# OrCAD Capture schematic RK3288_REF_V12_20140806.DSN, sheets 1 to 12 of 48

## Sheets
1 01.Index: title: Index; note: Index
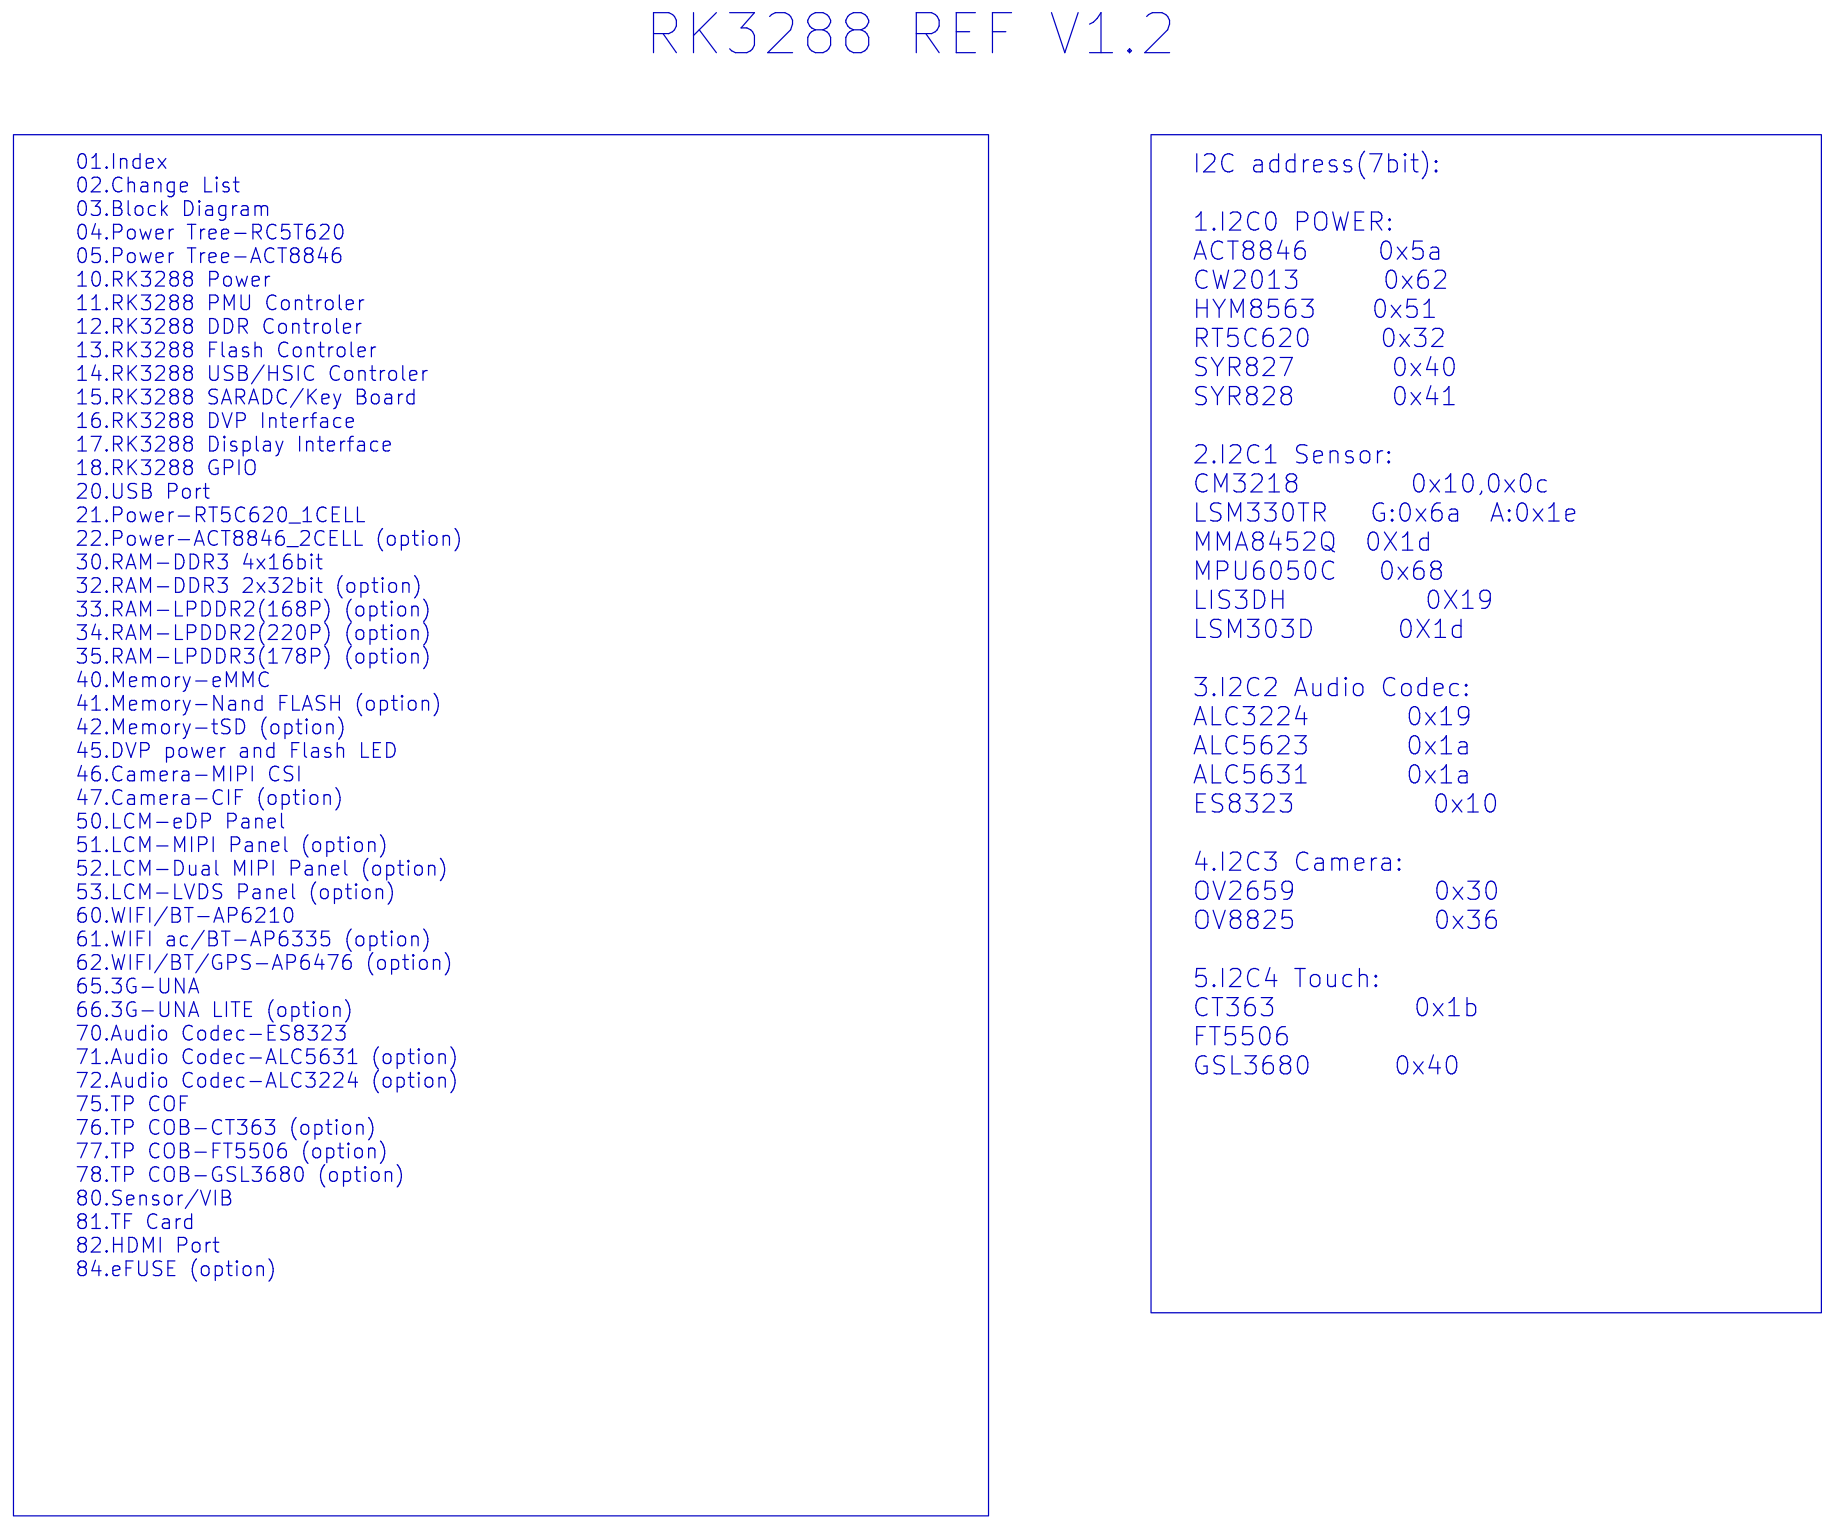
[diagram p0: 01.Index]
2 02.Change List: title: Change List; note: Change List
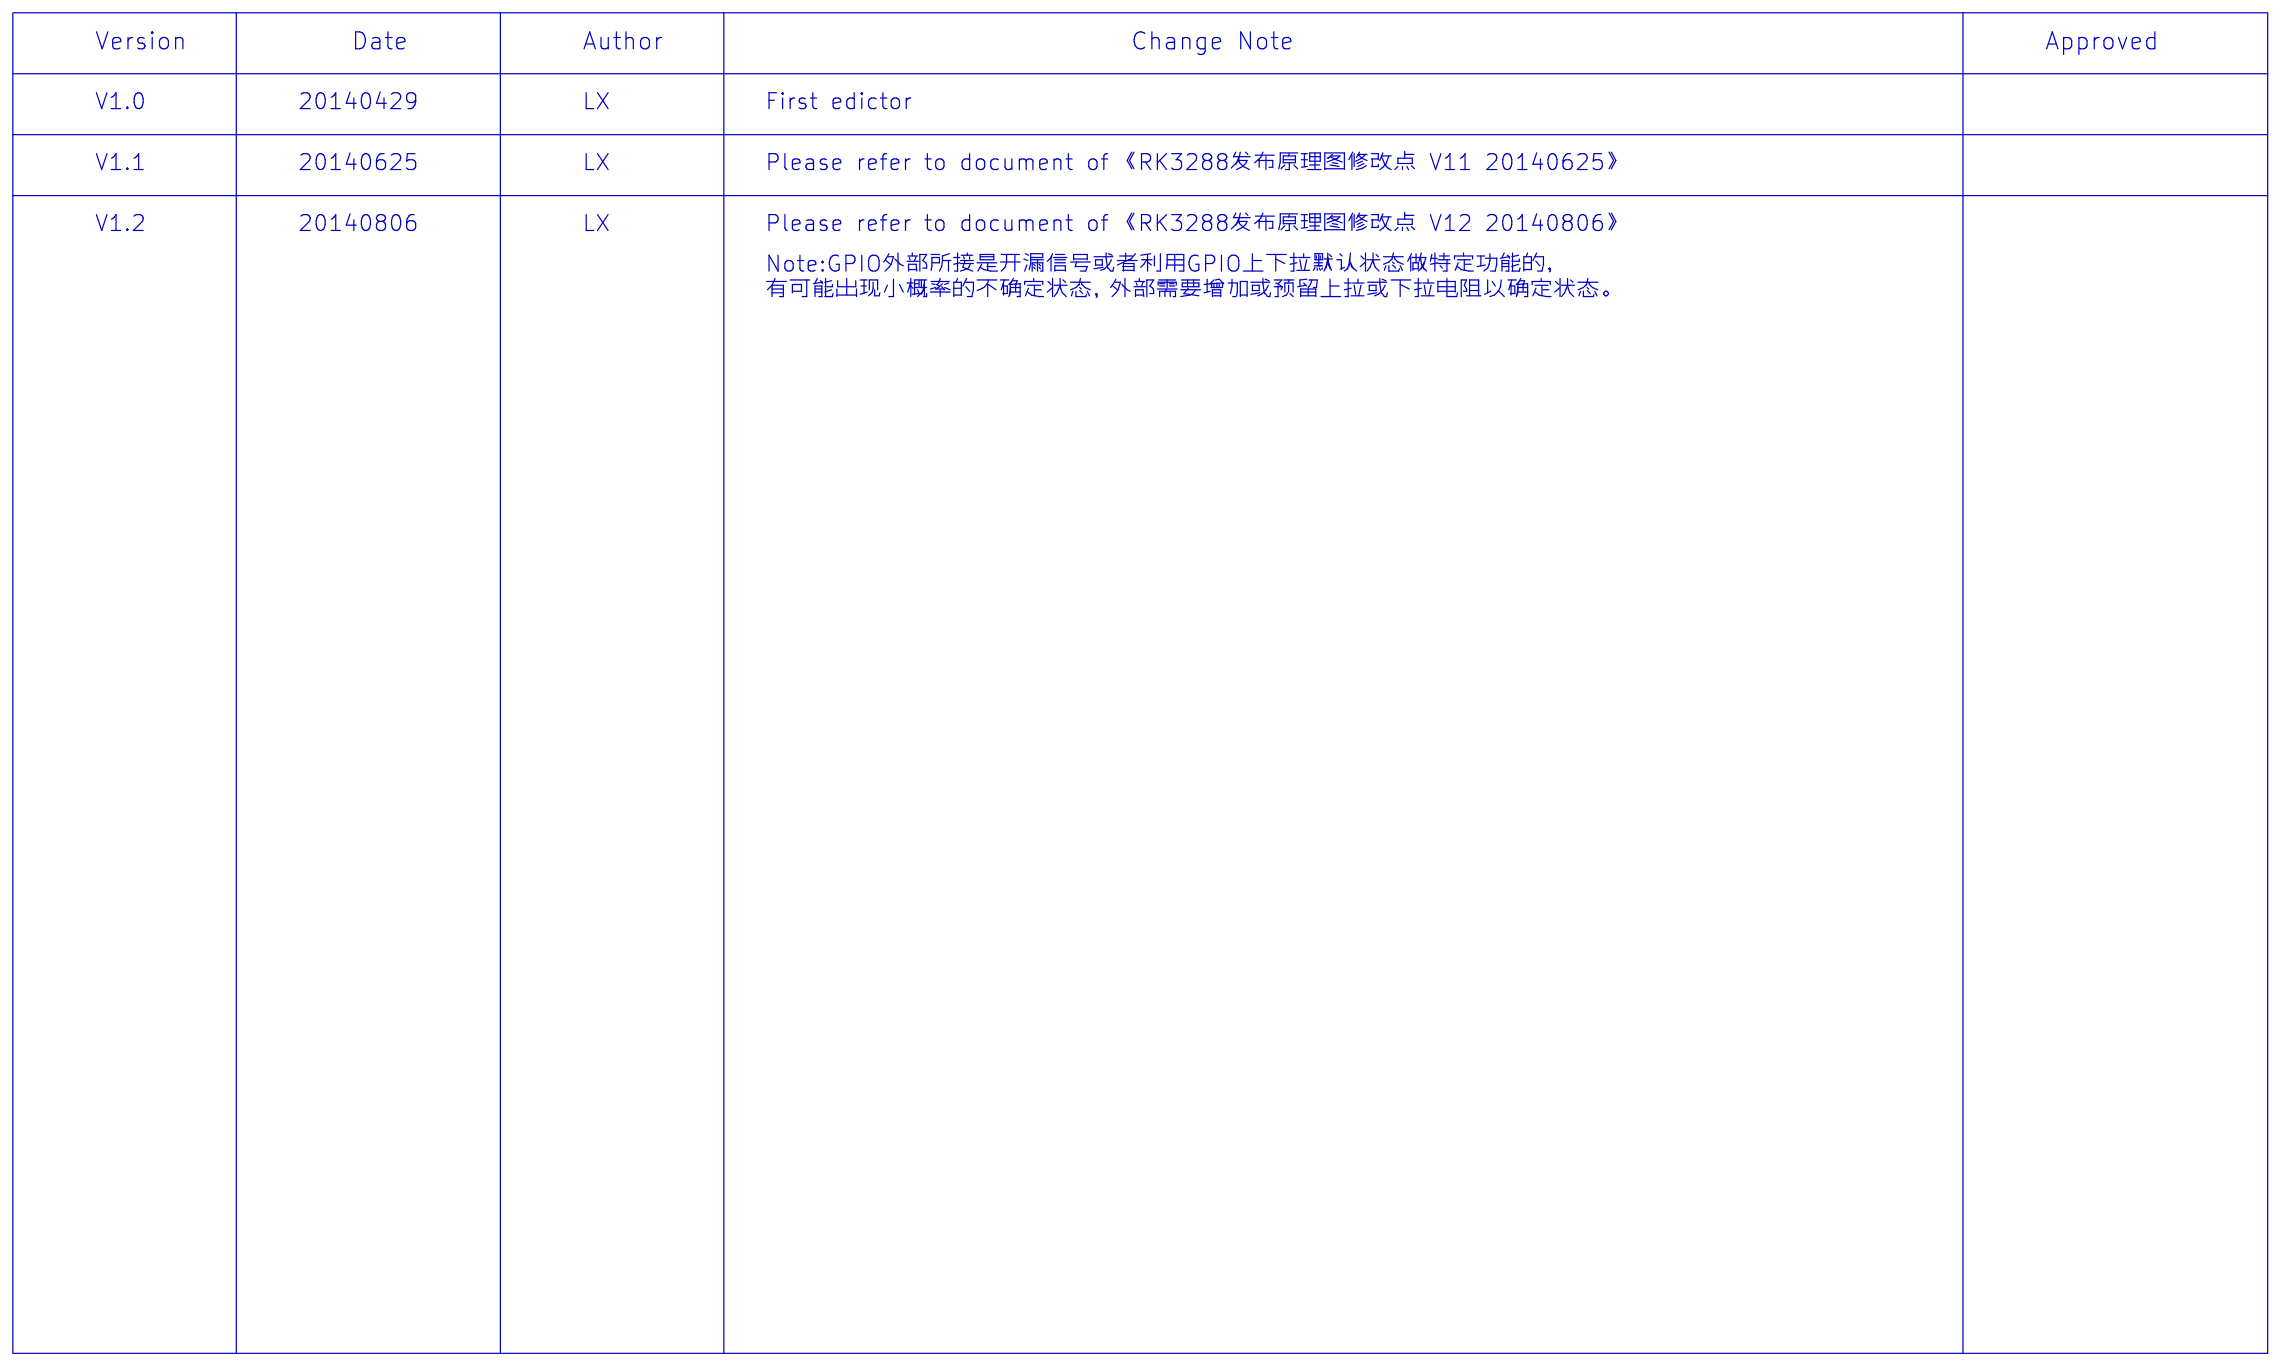
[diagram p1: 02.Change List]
3 03.Block Diagram: title: Block Diagram; note: Block Diagram
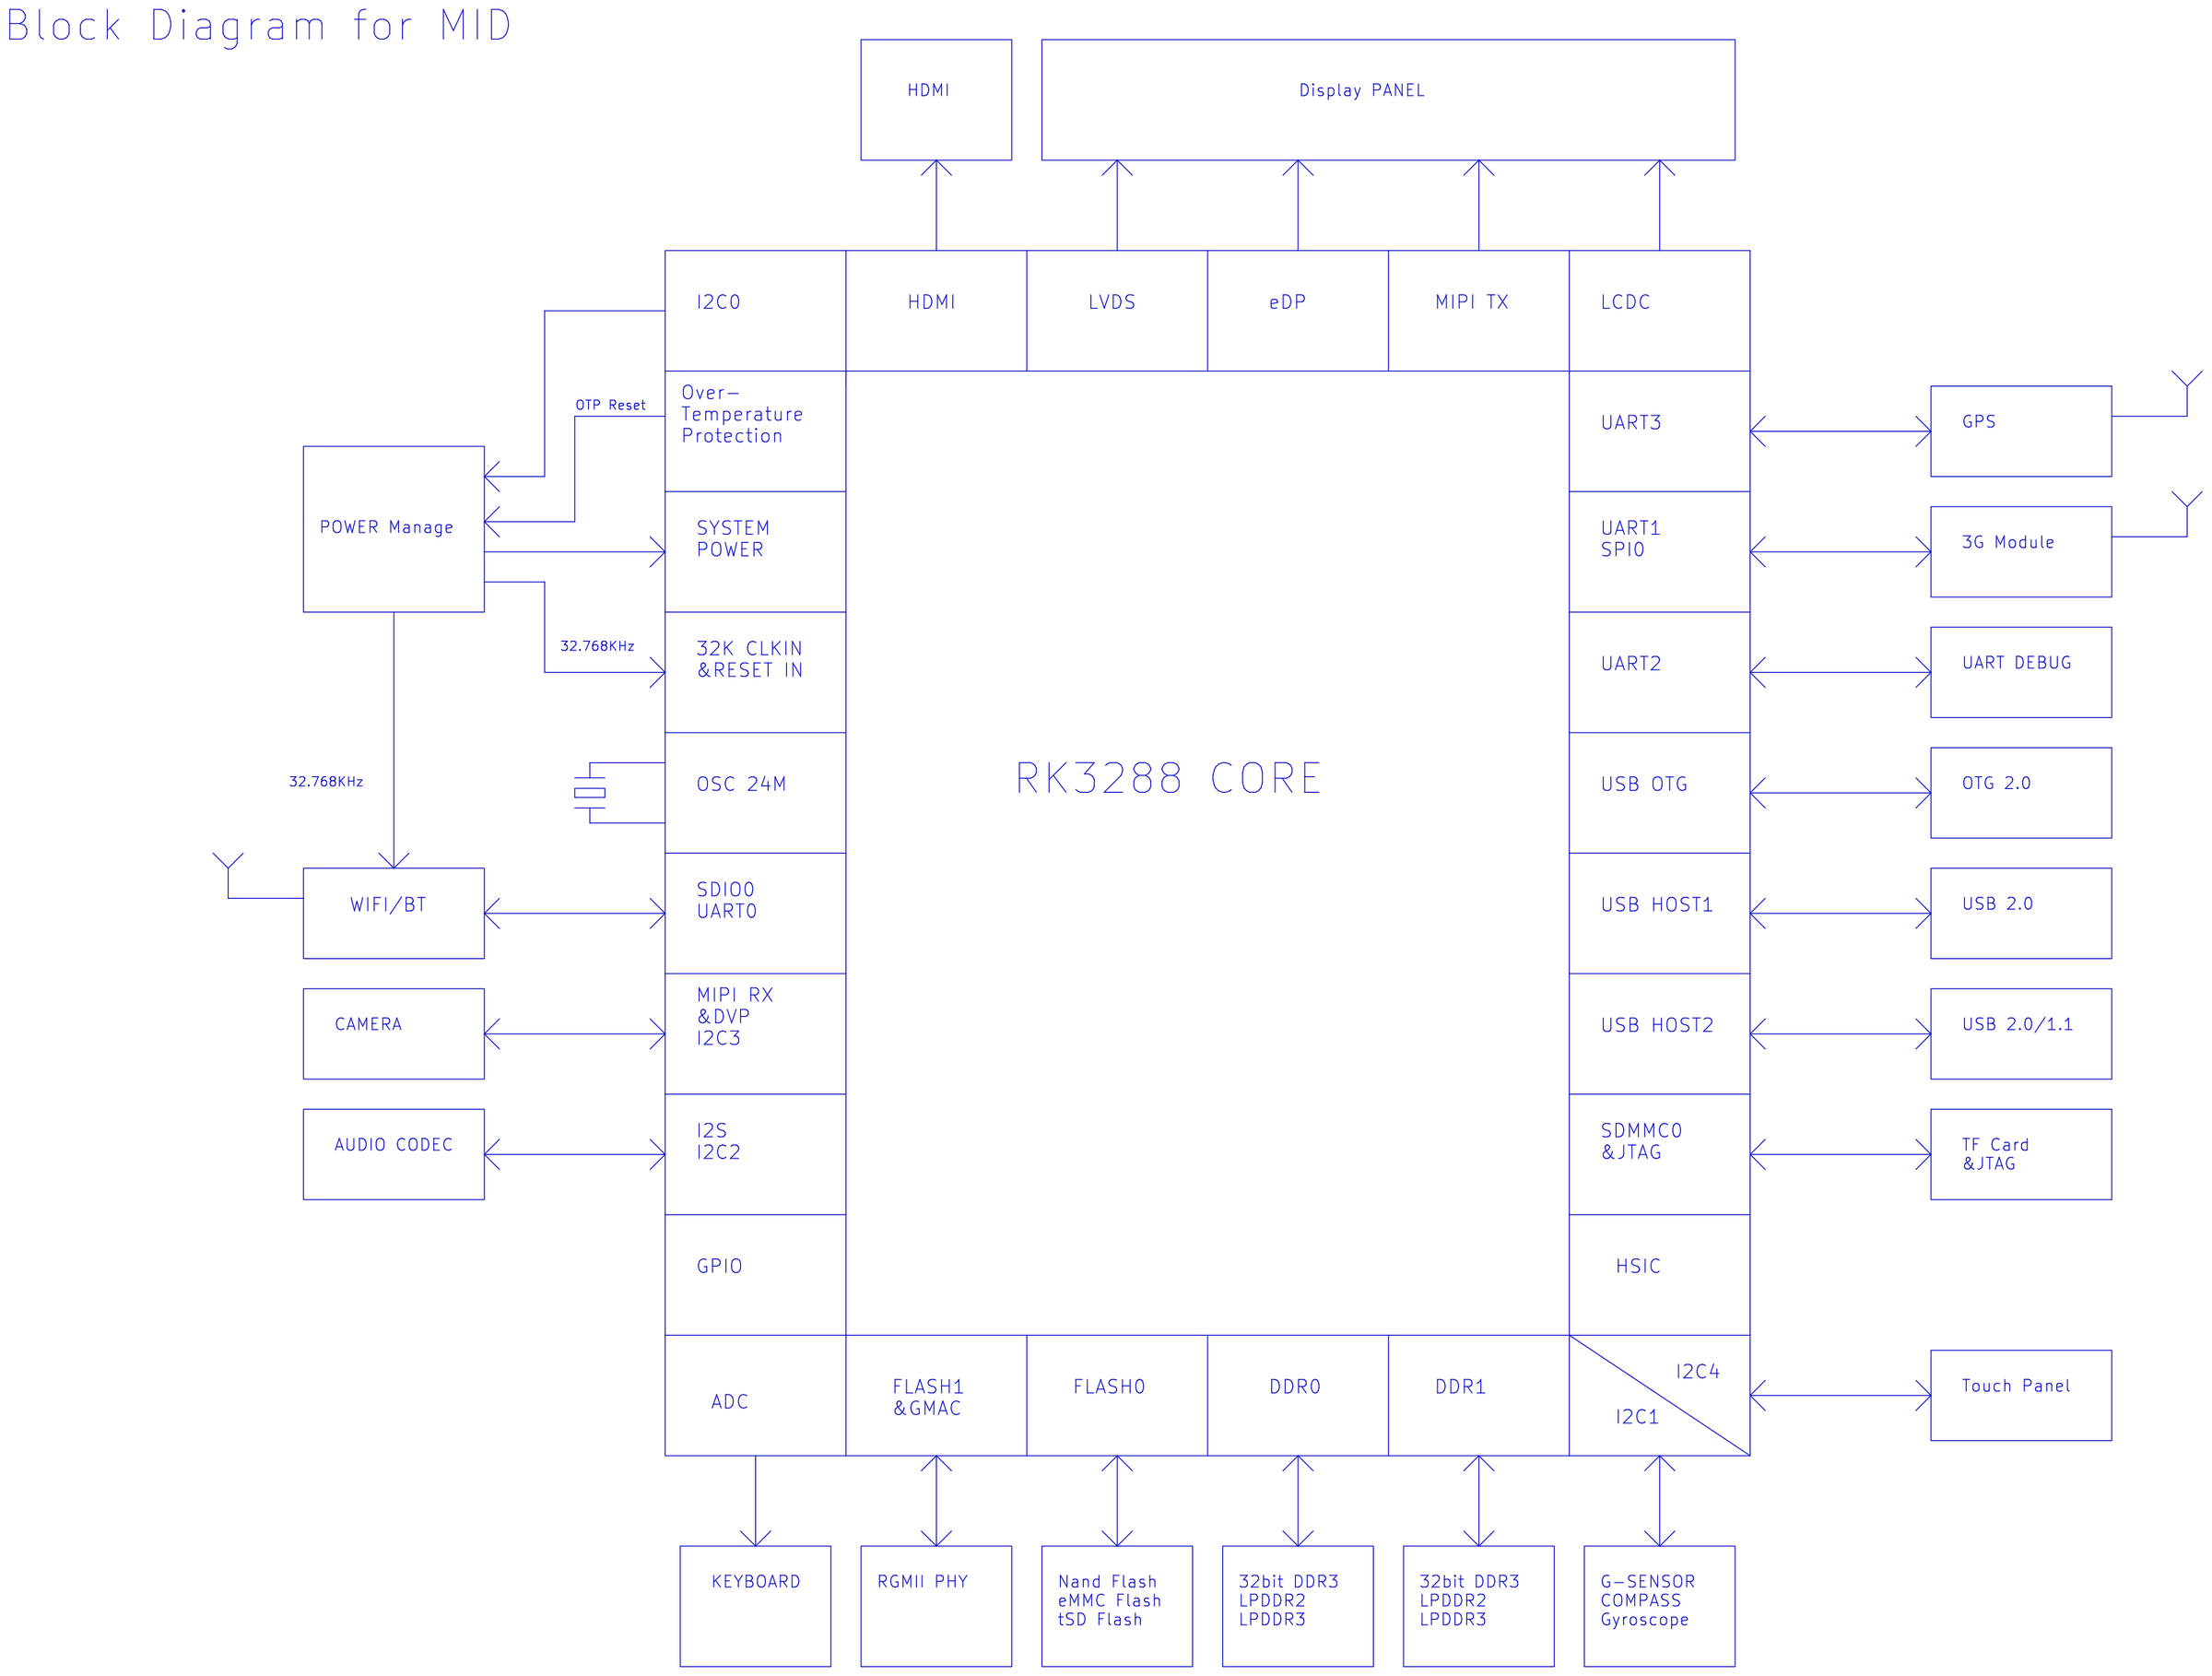
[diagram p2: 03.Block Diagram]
4 05.Power Tree-ACT8846: title: Power Tree; note: Power Tree
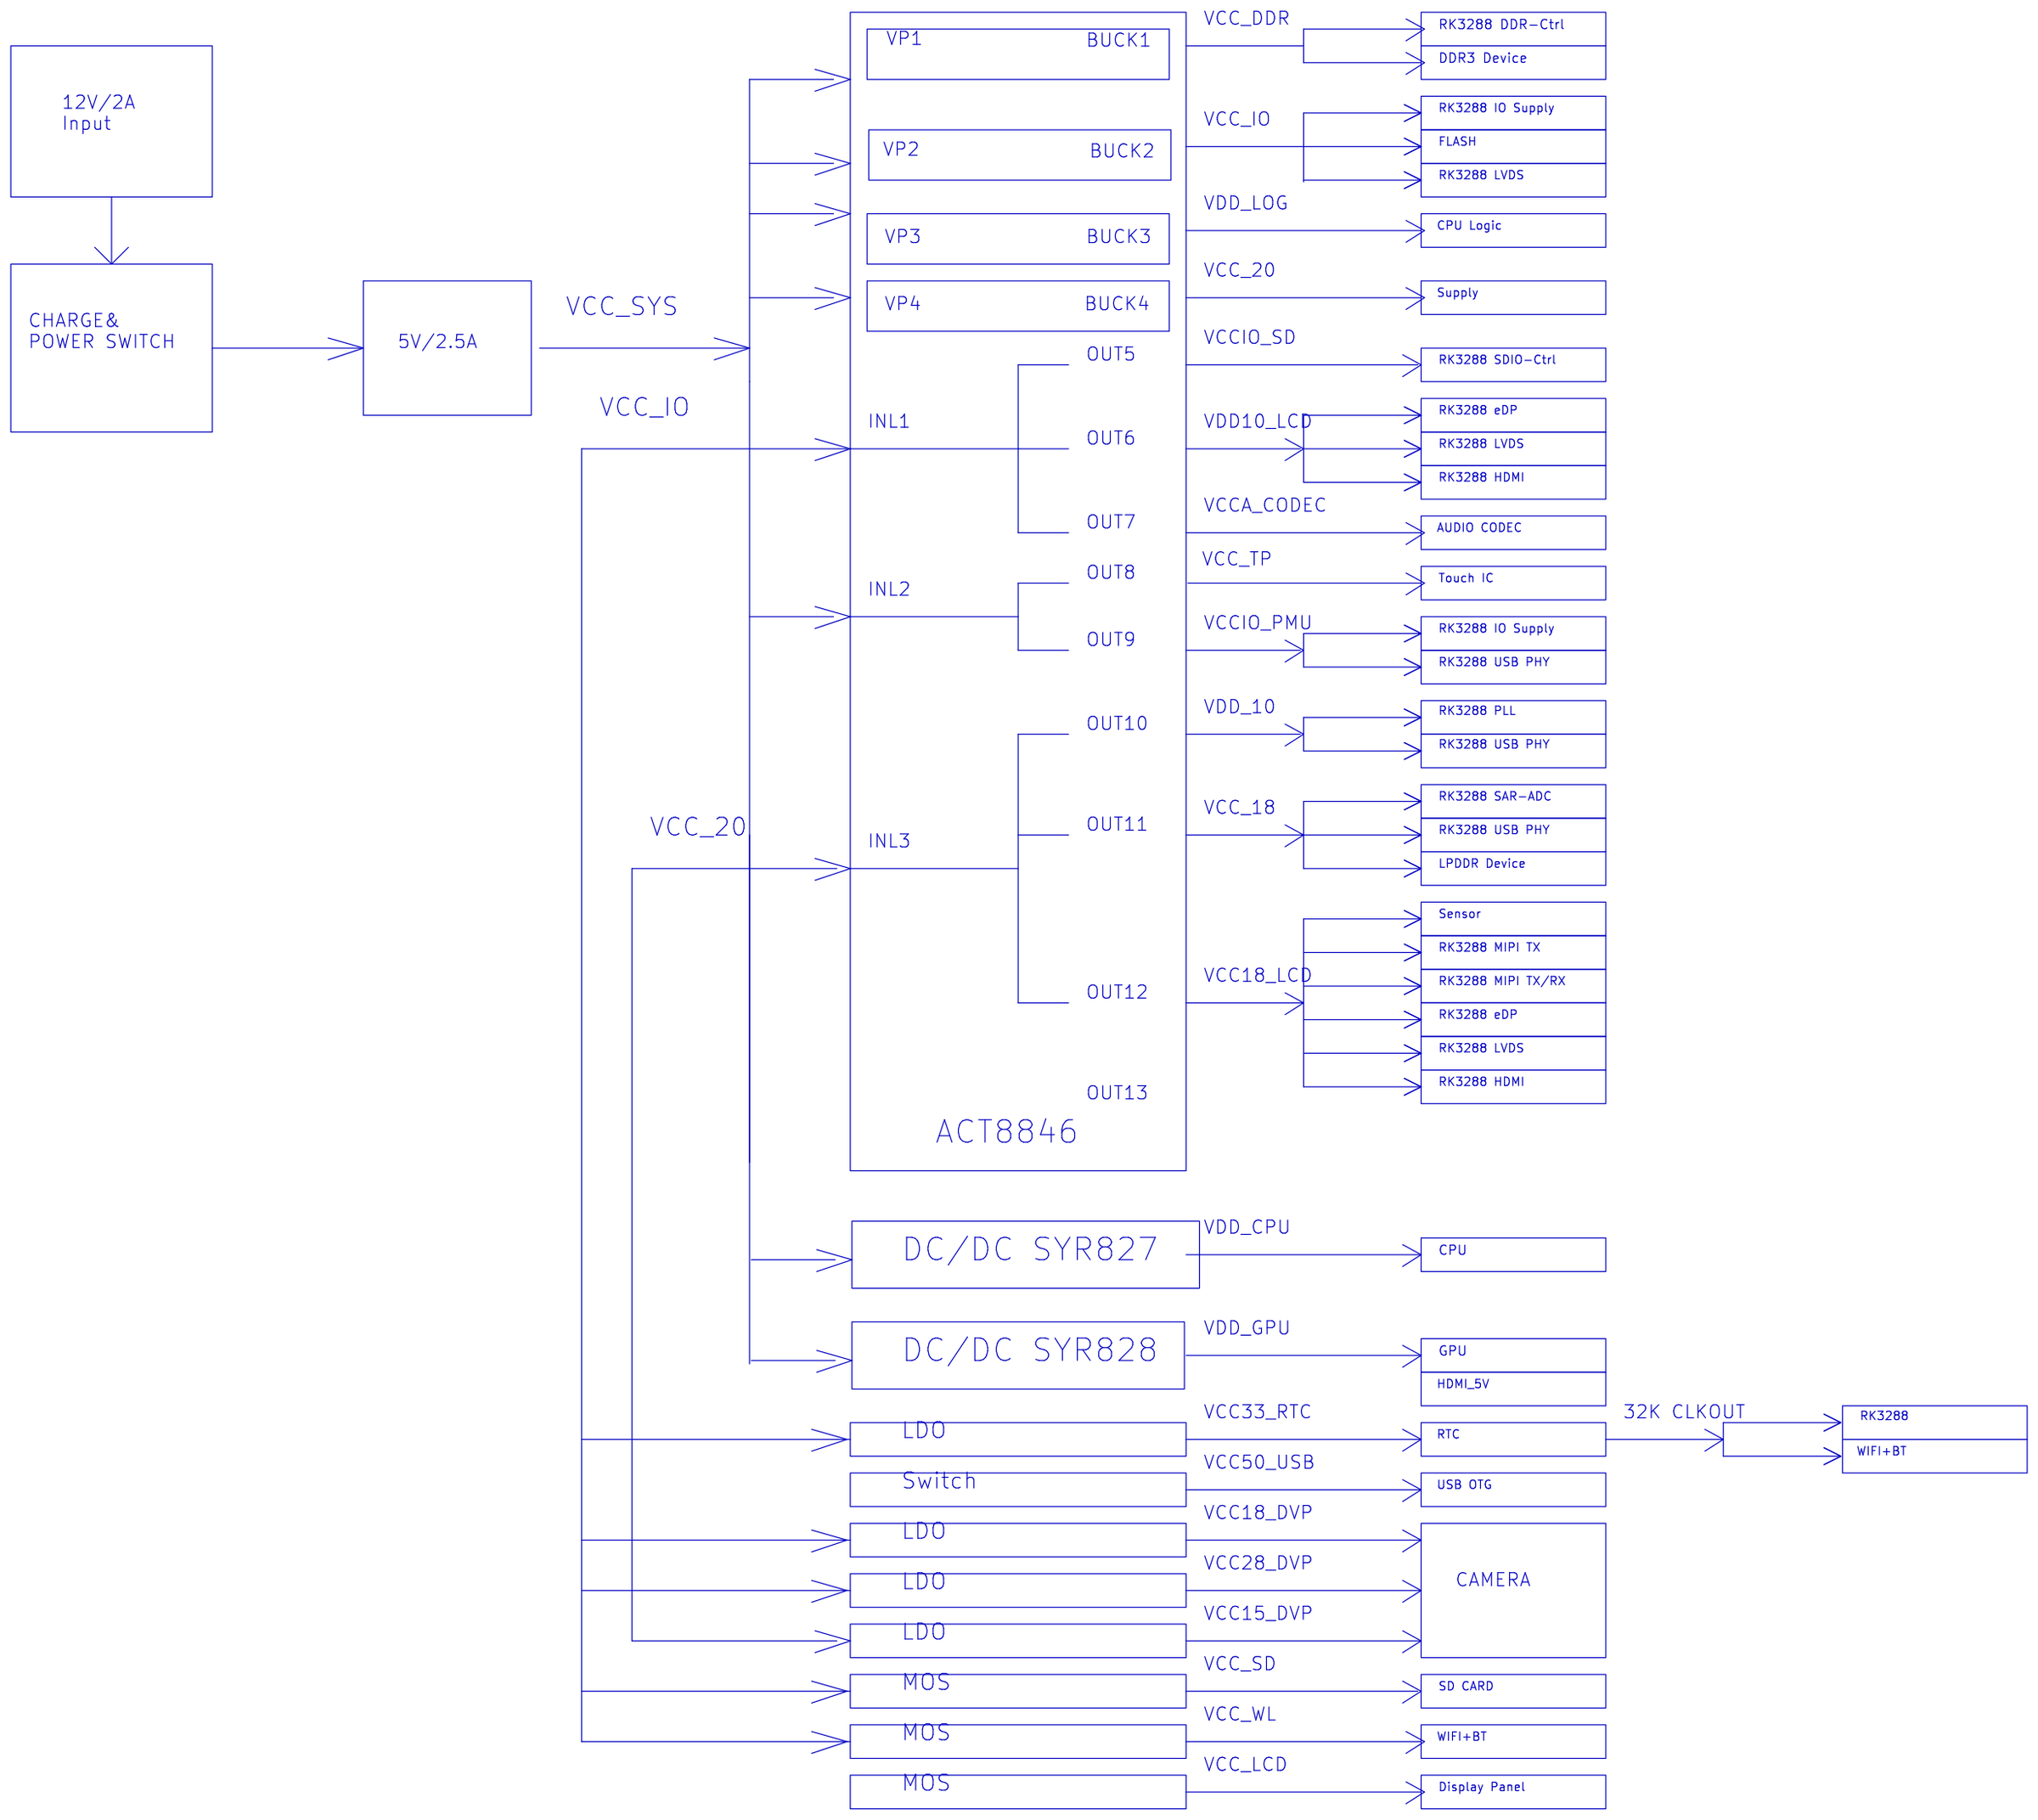
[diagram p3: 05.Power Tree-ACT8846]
5 10.RK3288 Power: size A4; title: RK3288 Power; note: RK3288 Power
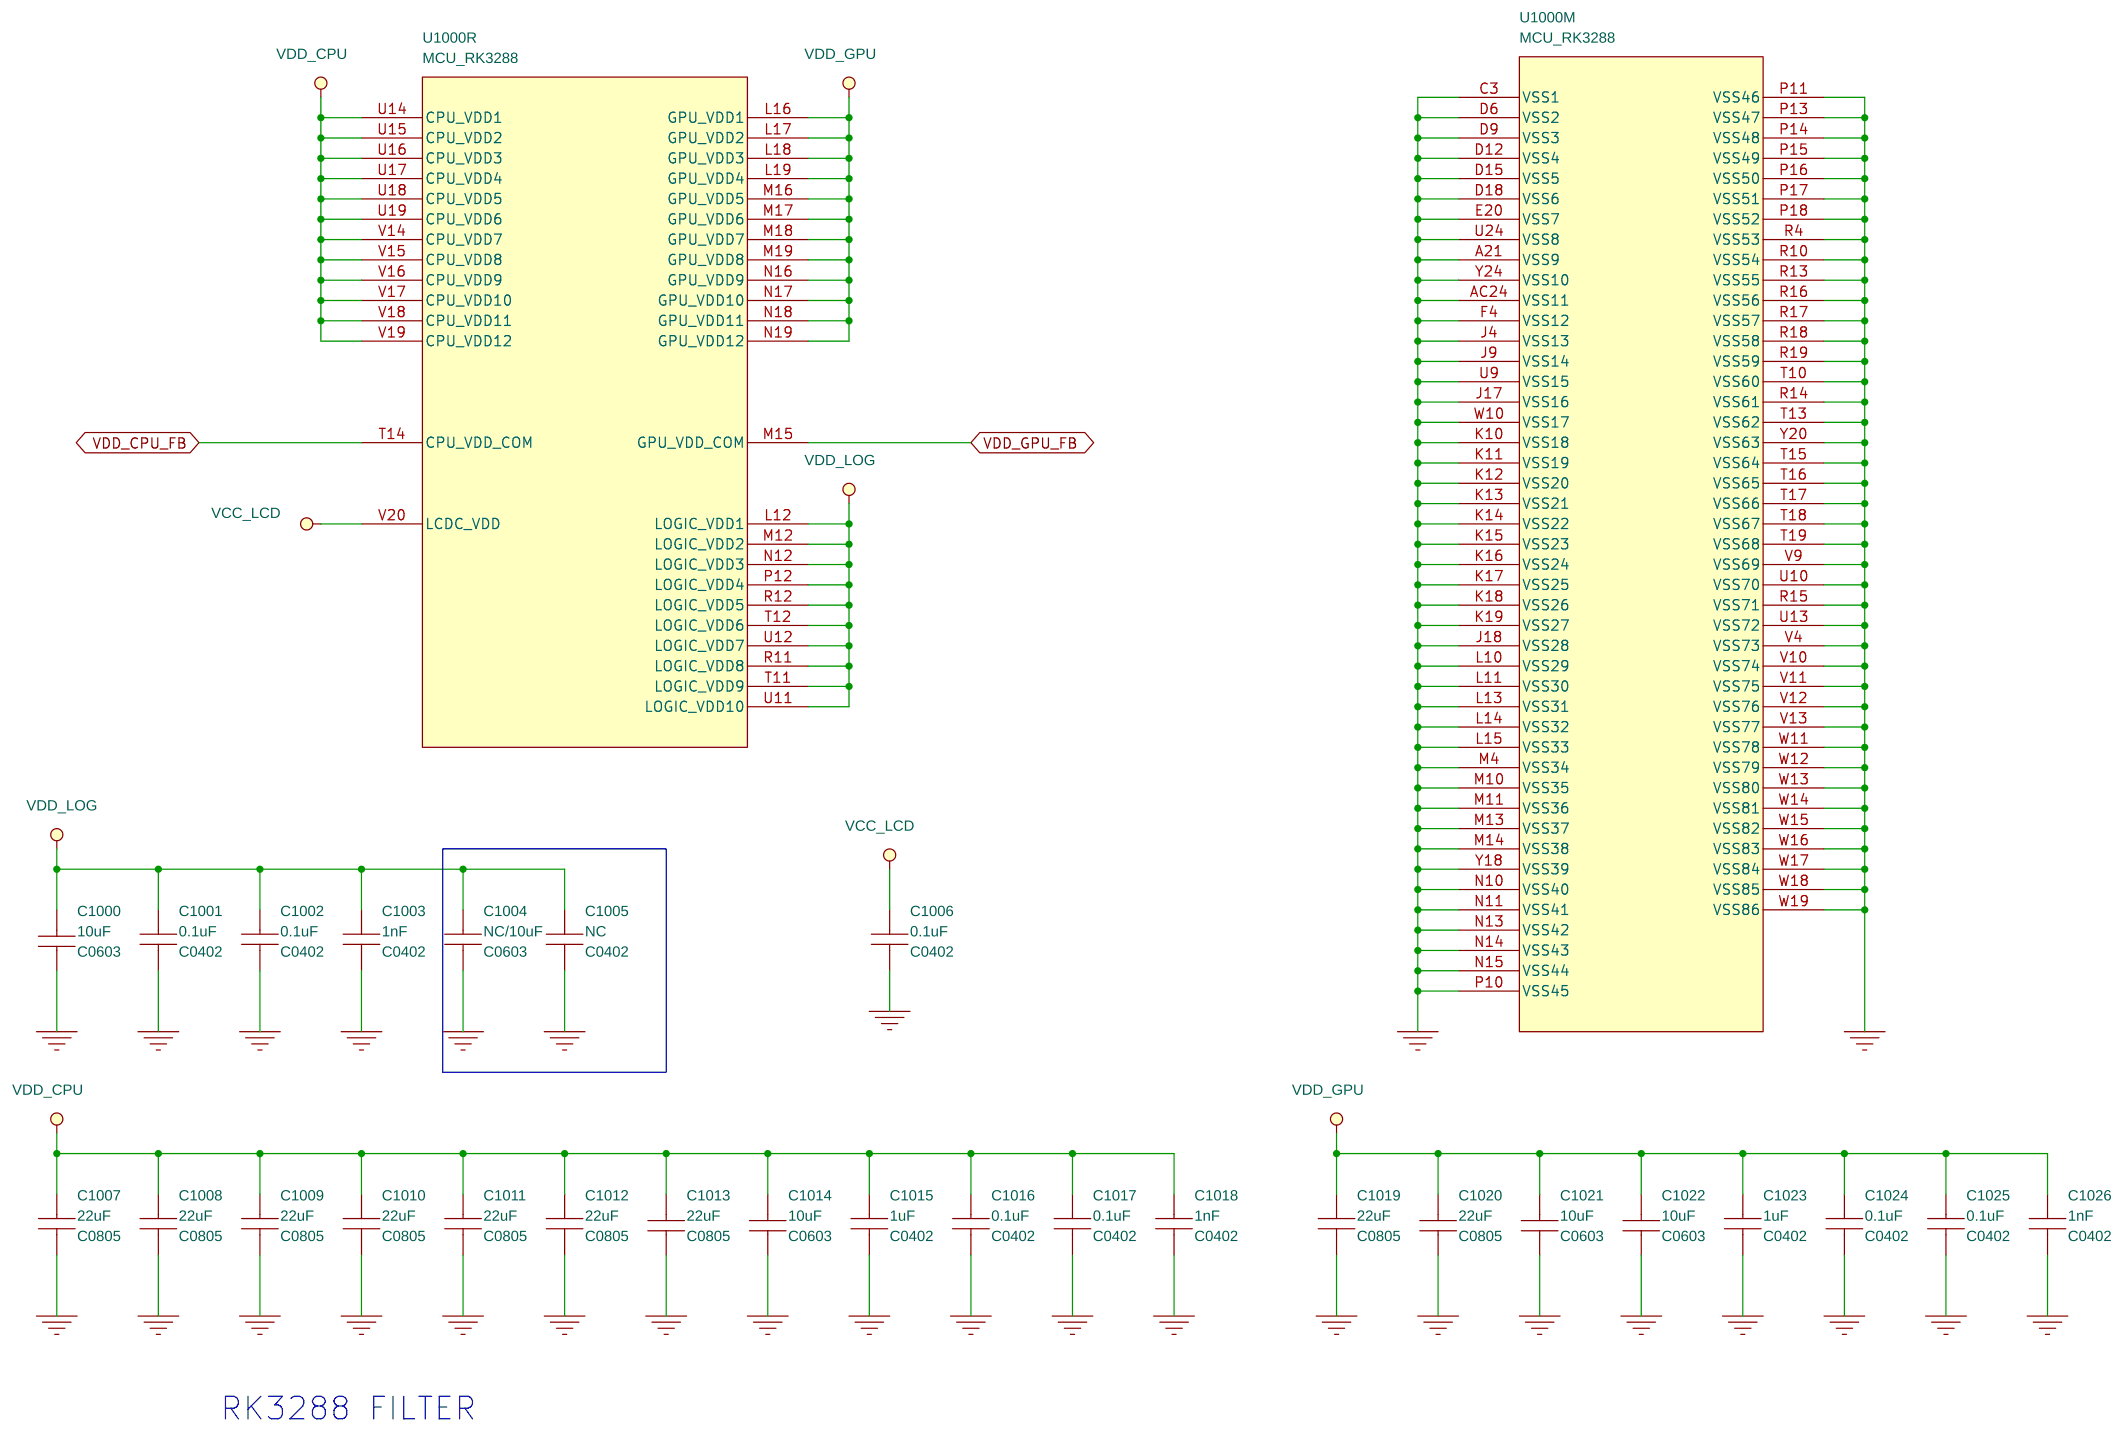
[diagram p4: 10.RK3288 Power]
6 11.RK3288 PMU Controler: size A4; title: RK3288 PMU Controler; note: RK3288 PMU Controler
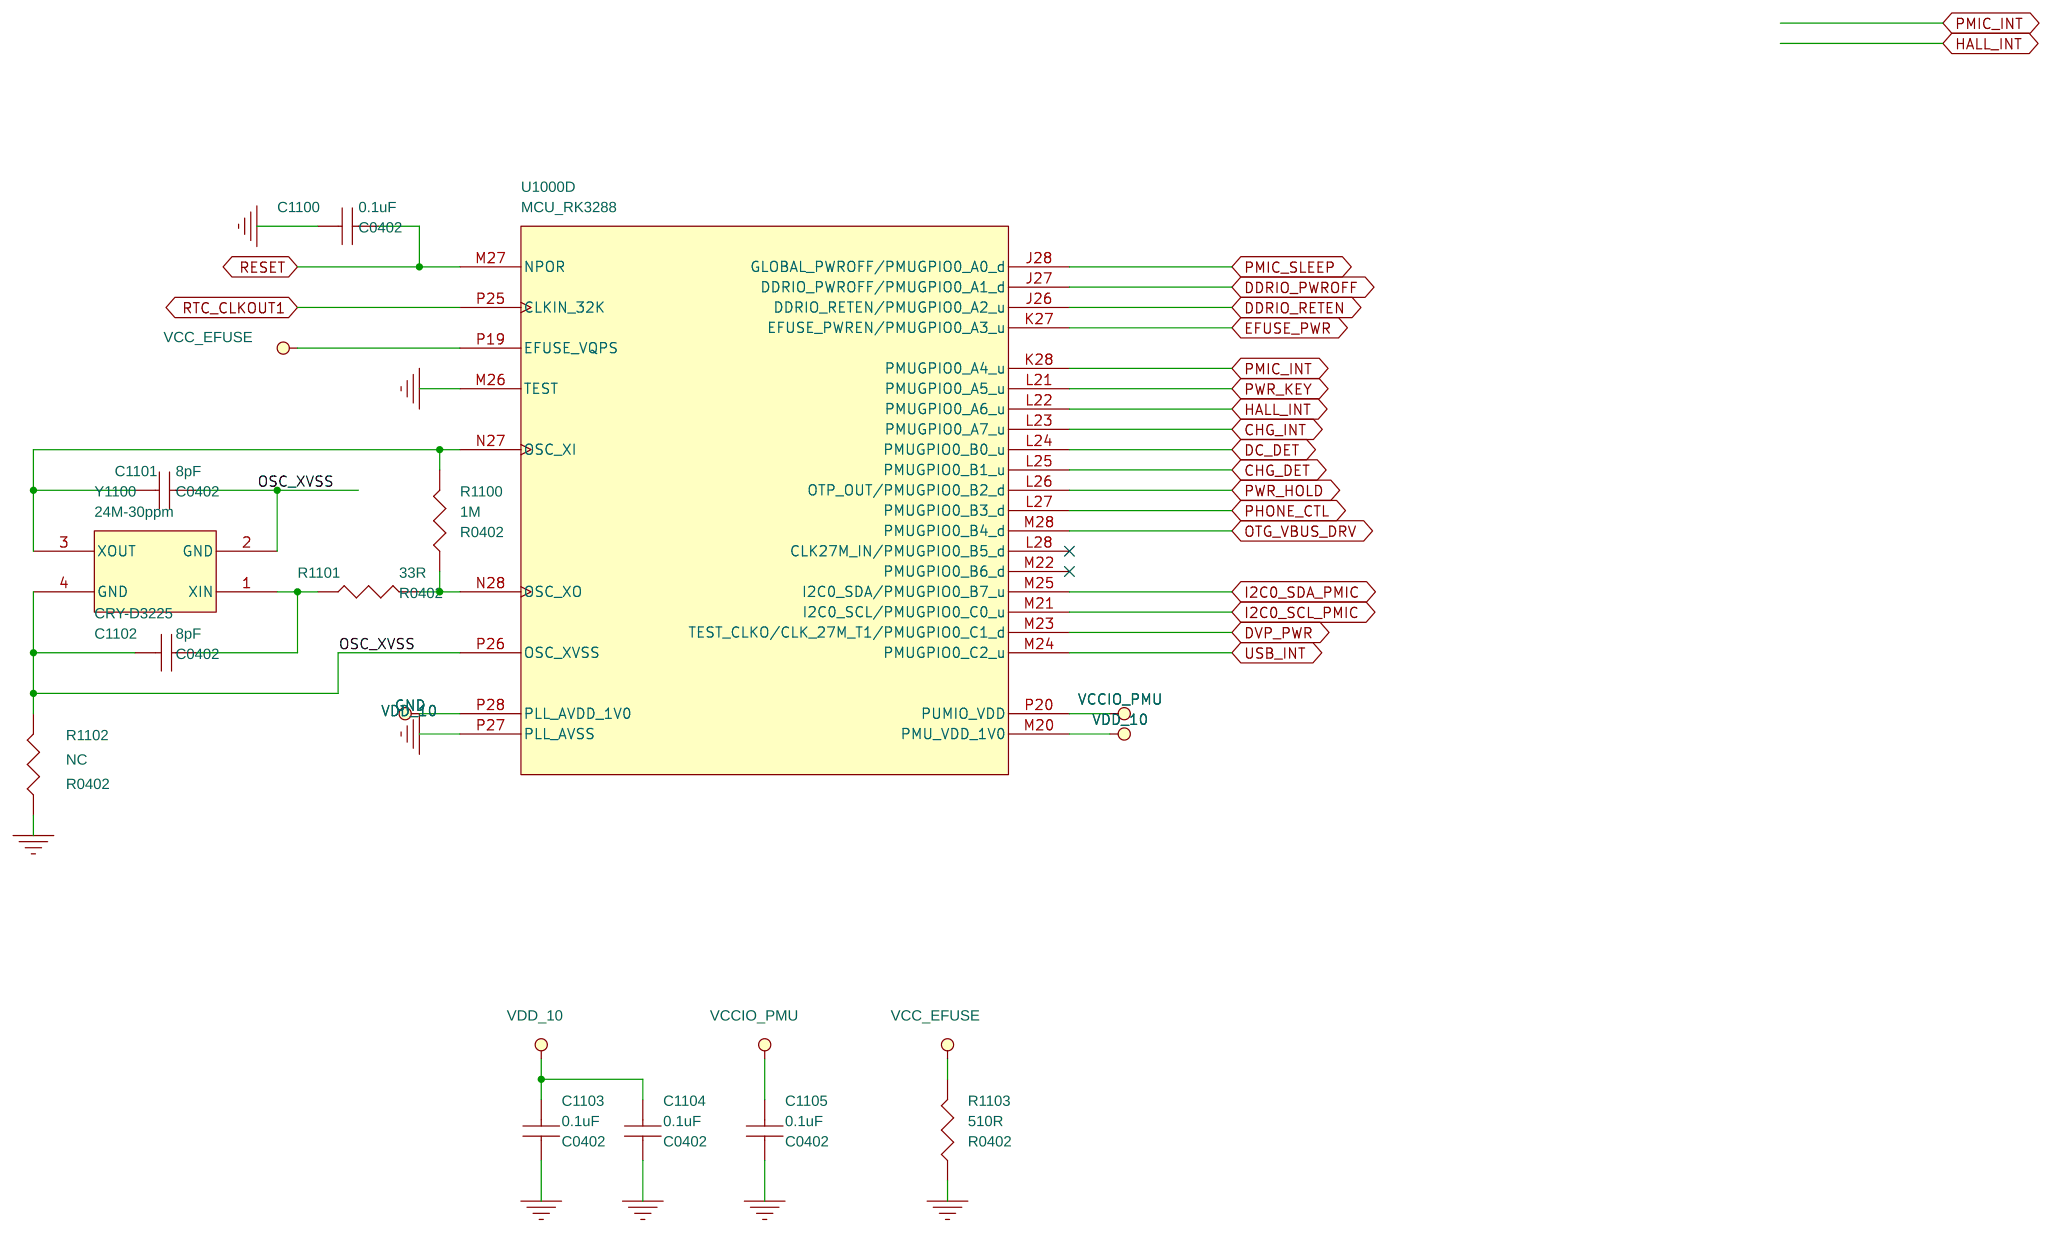
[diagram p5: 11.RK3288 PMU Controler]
7 12.RK3288 DDR Controler: size A3; title: RK3288 DDR Controler; note: RK3288 DDR Control
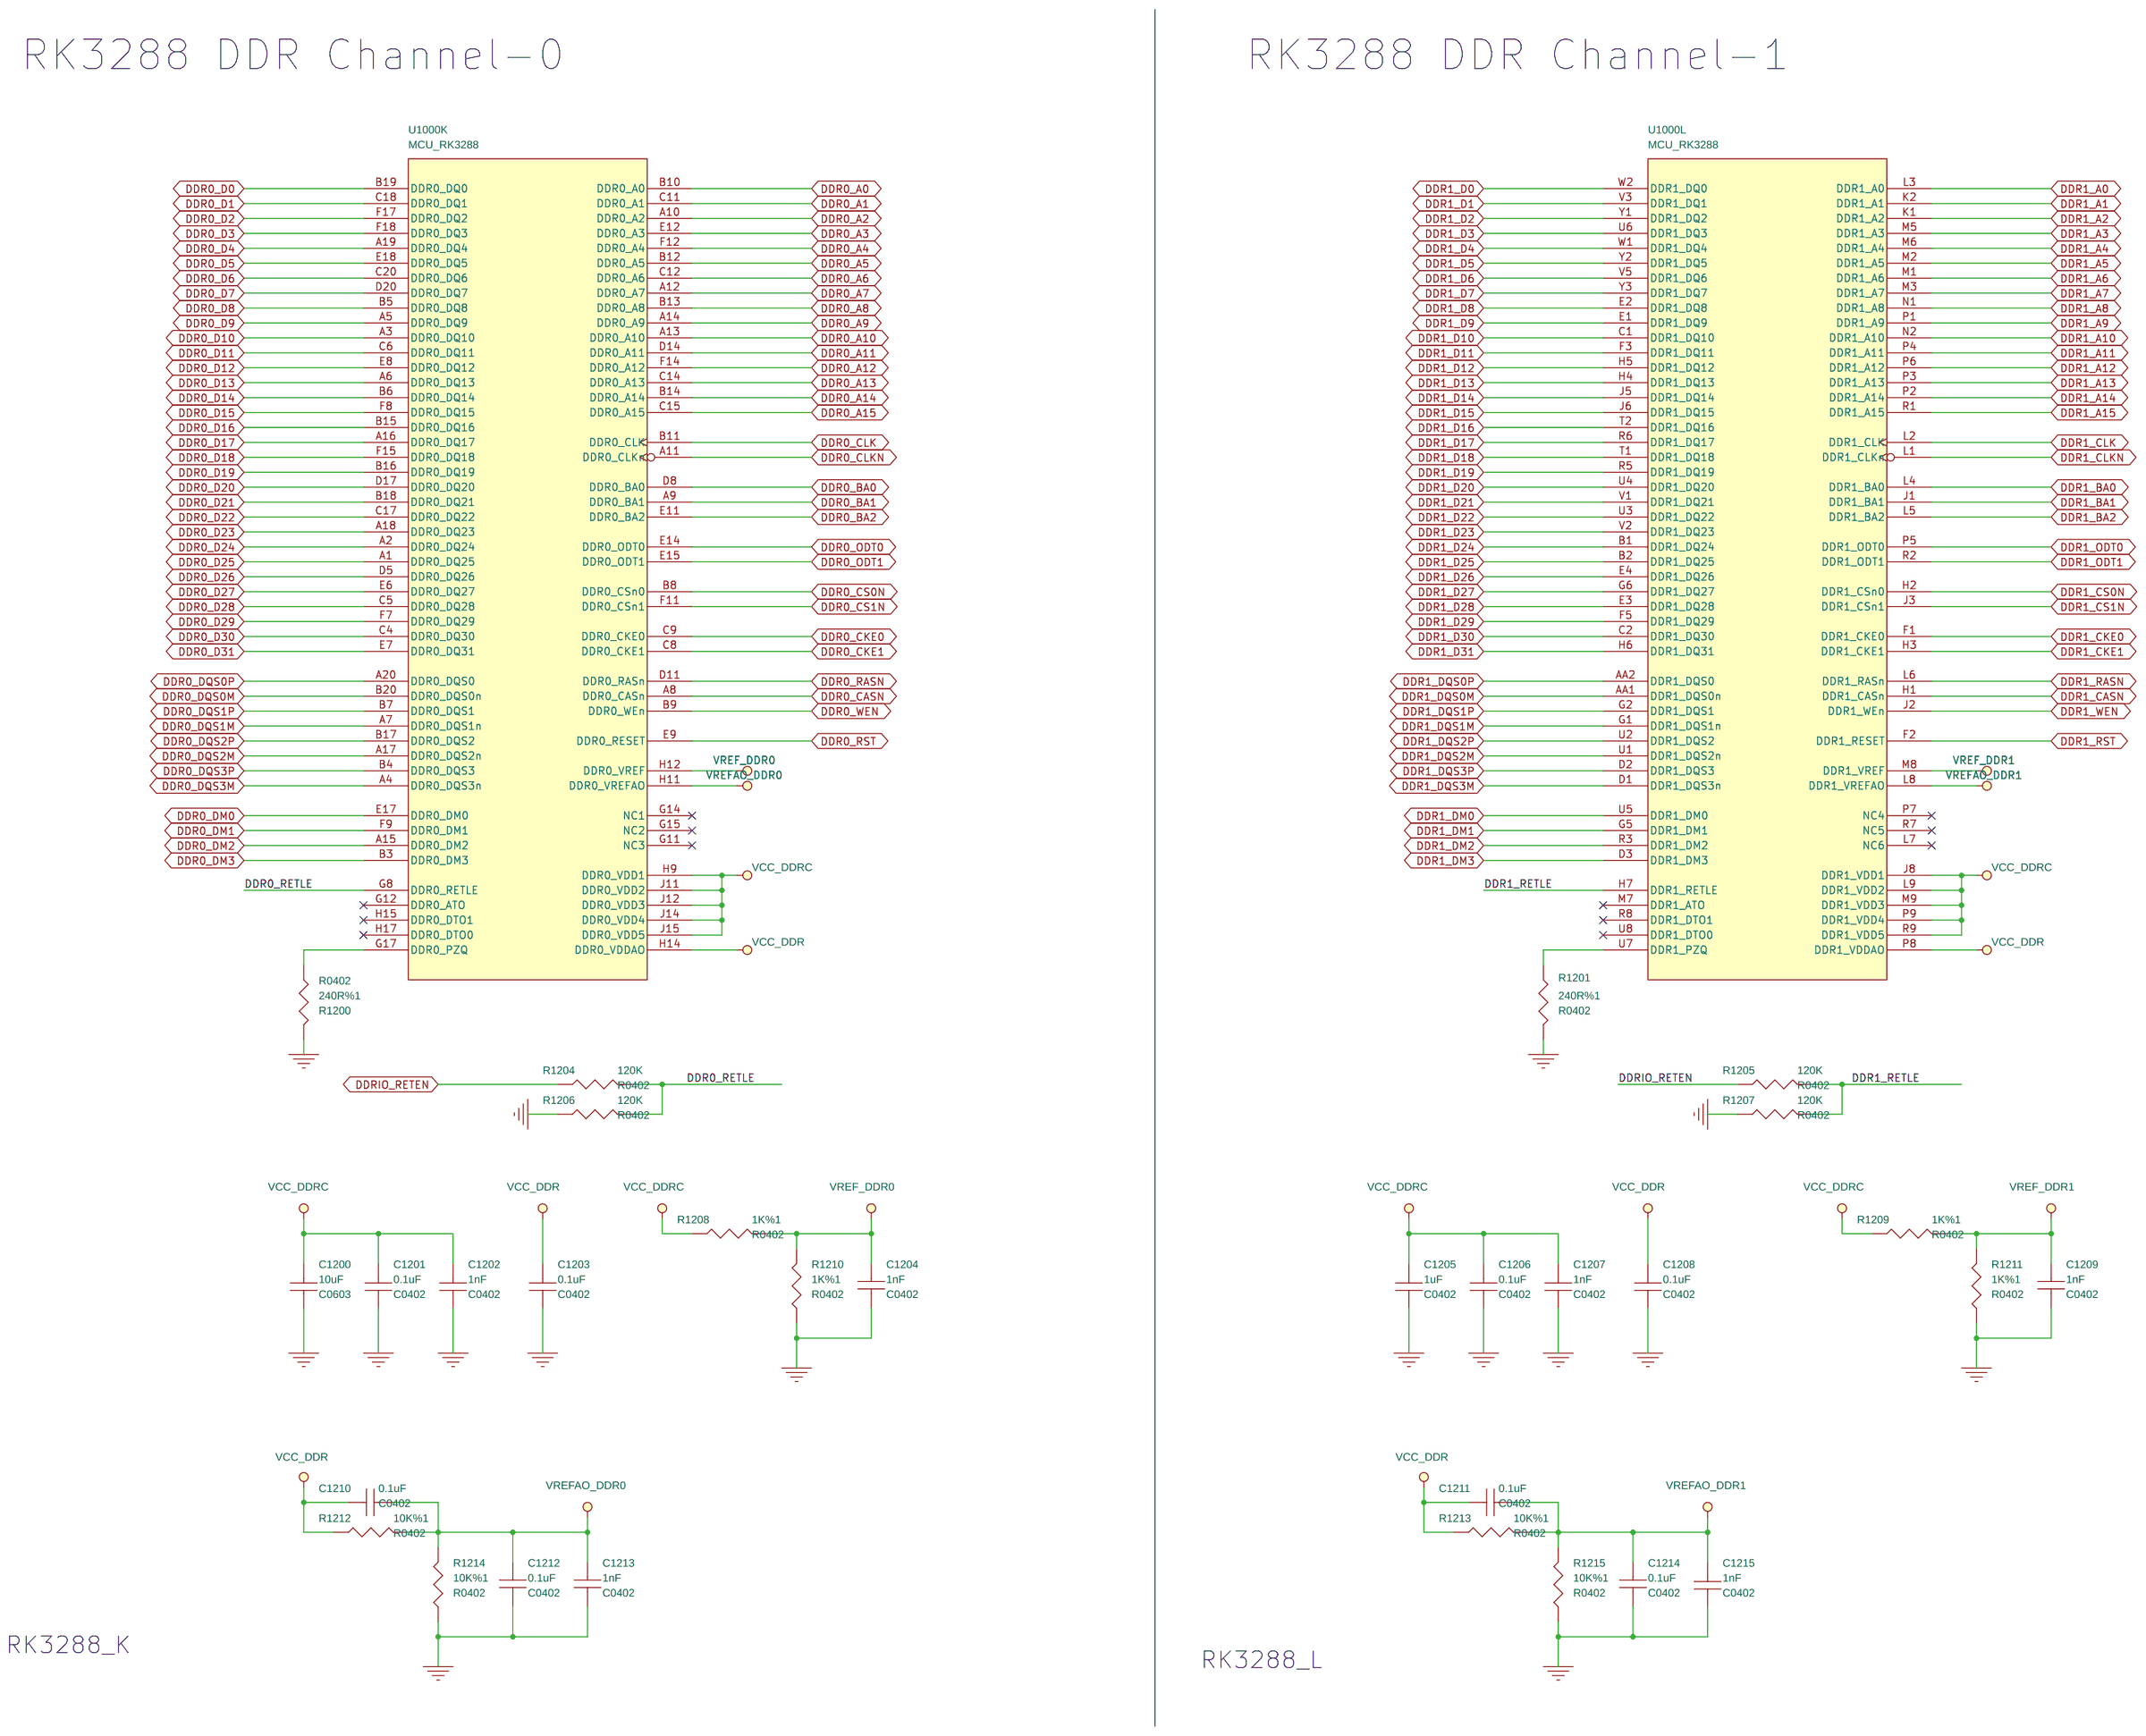
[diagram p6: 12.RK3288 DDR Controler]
8 13.RK3288 Flash Controler: size A4; title: RK3288 Flash Control; note: RK3288 Flash Control
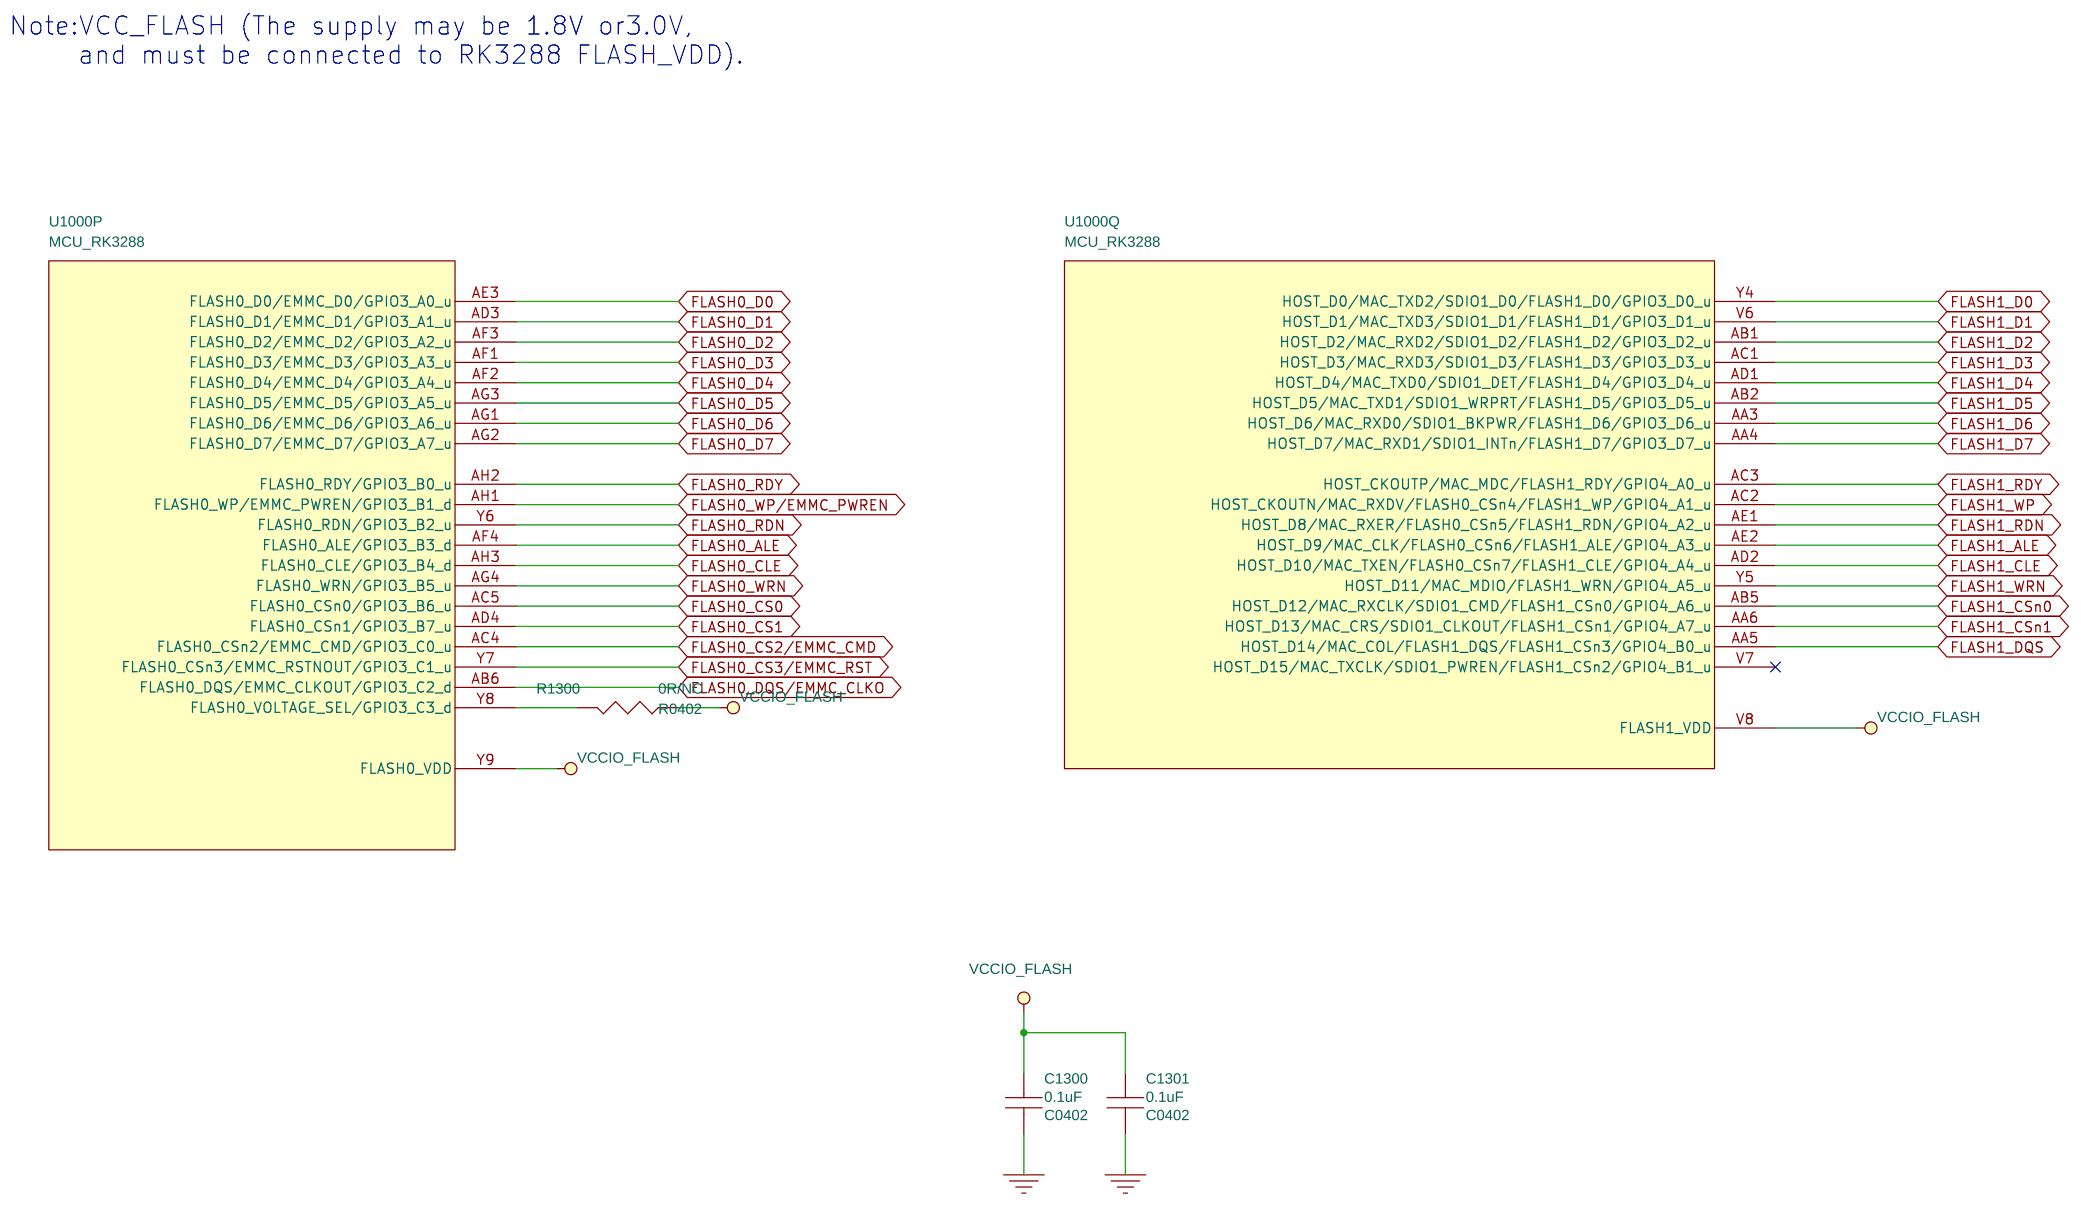
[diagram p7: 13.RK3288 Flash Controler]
9 16.RK3288 DVP Interface: size A4; title: RK3288 DVP Interface; note: RK3288 DVP Interface
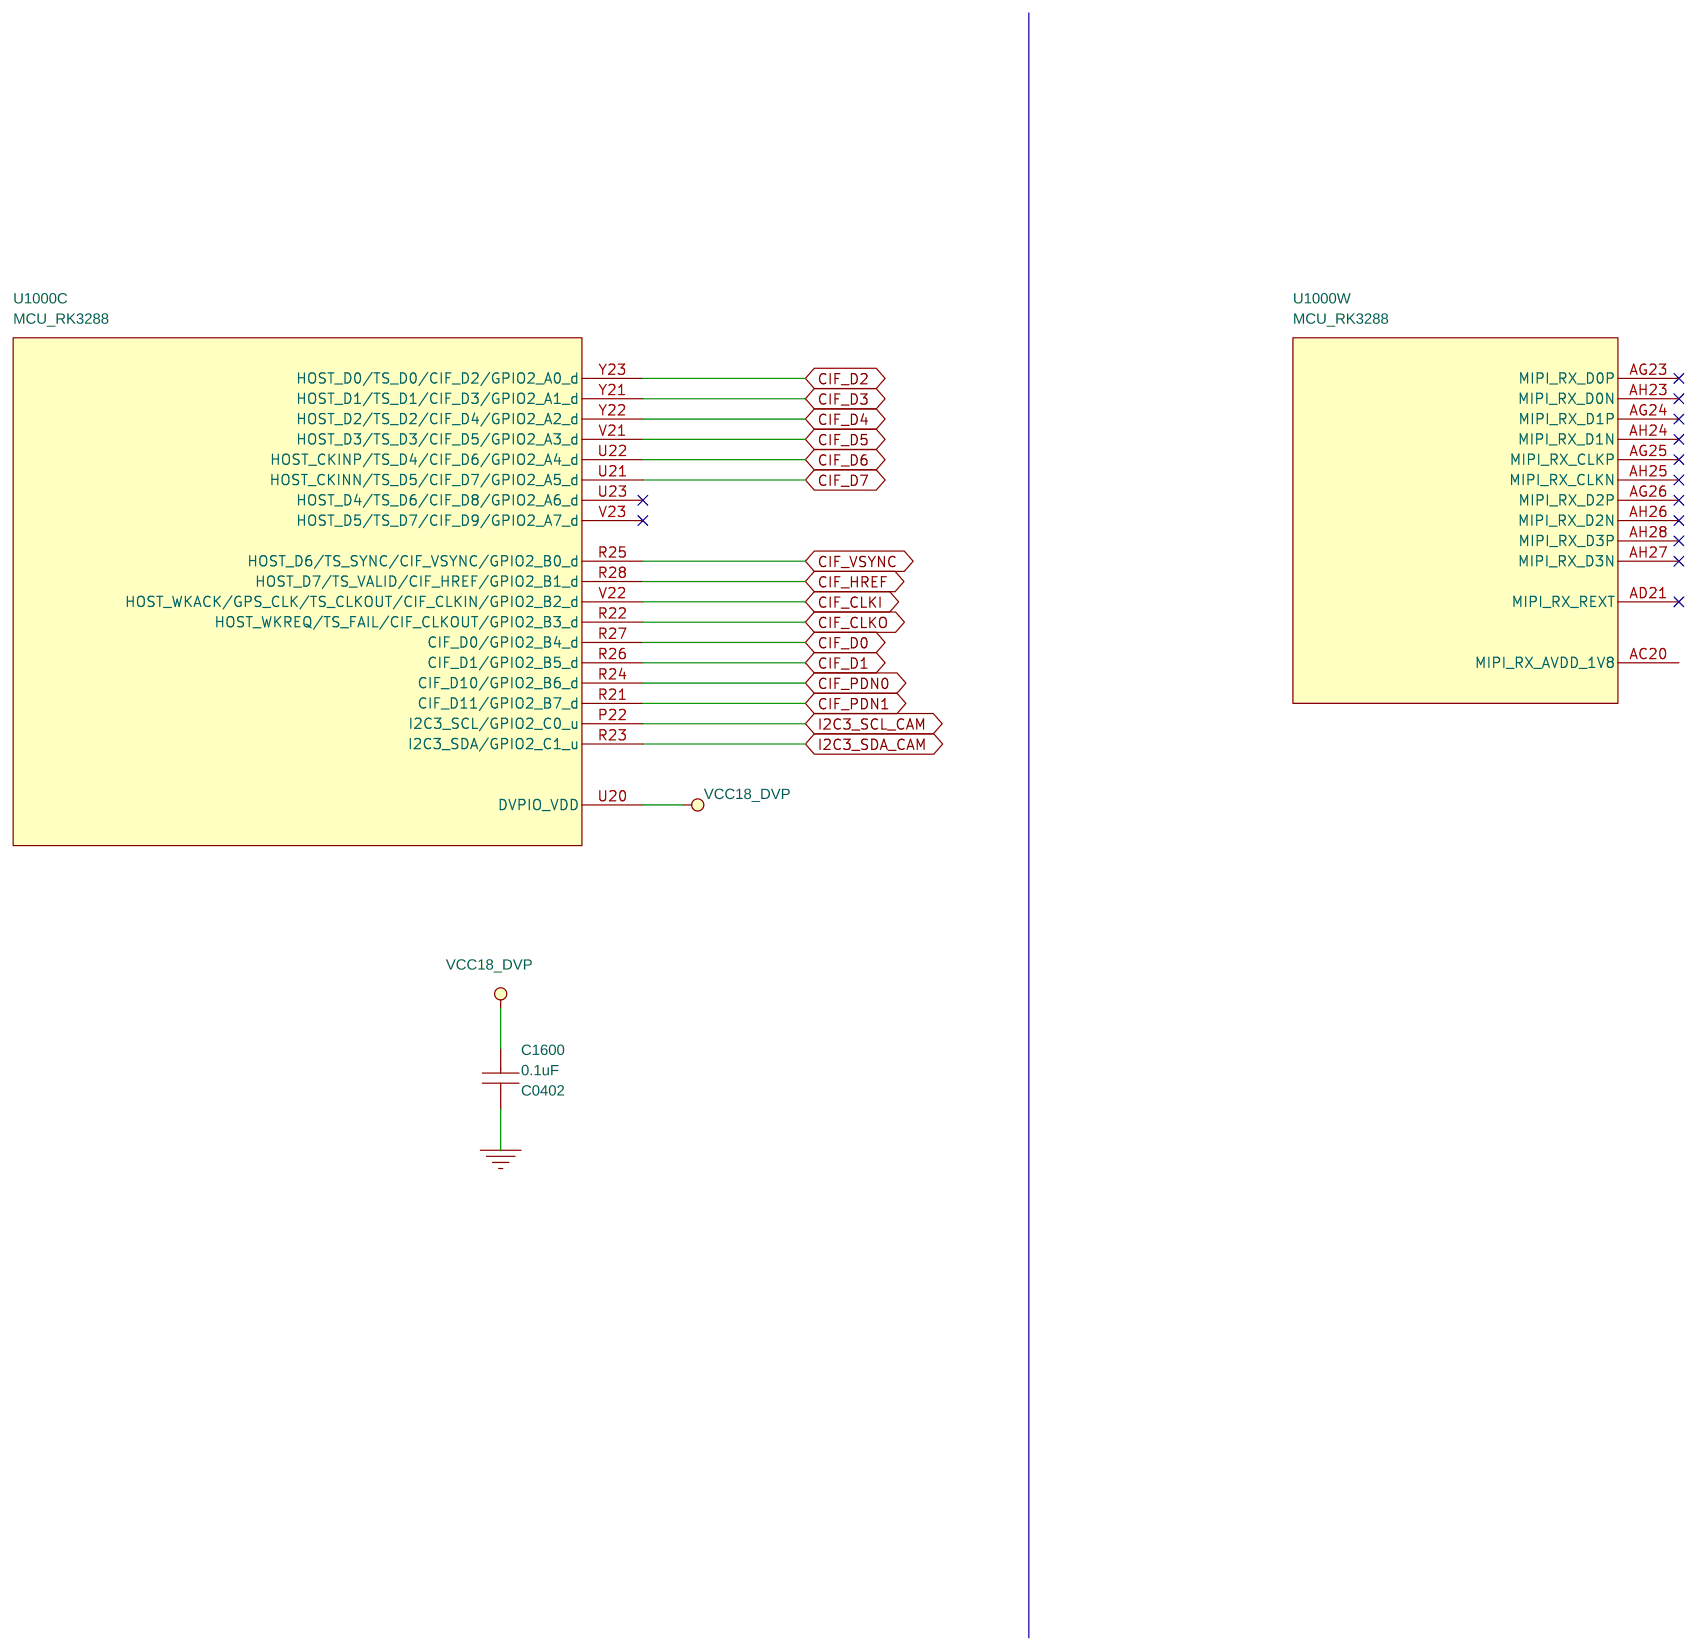
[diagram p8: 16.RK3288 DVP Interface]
10 17.RK3288 Display Interface: size A3; title: RK3288 Display Interface; note: RK3288 Display Interface
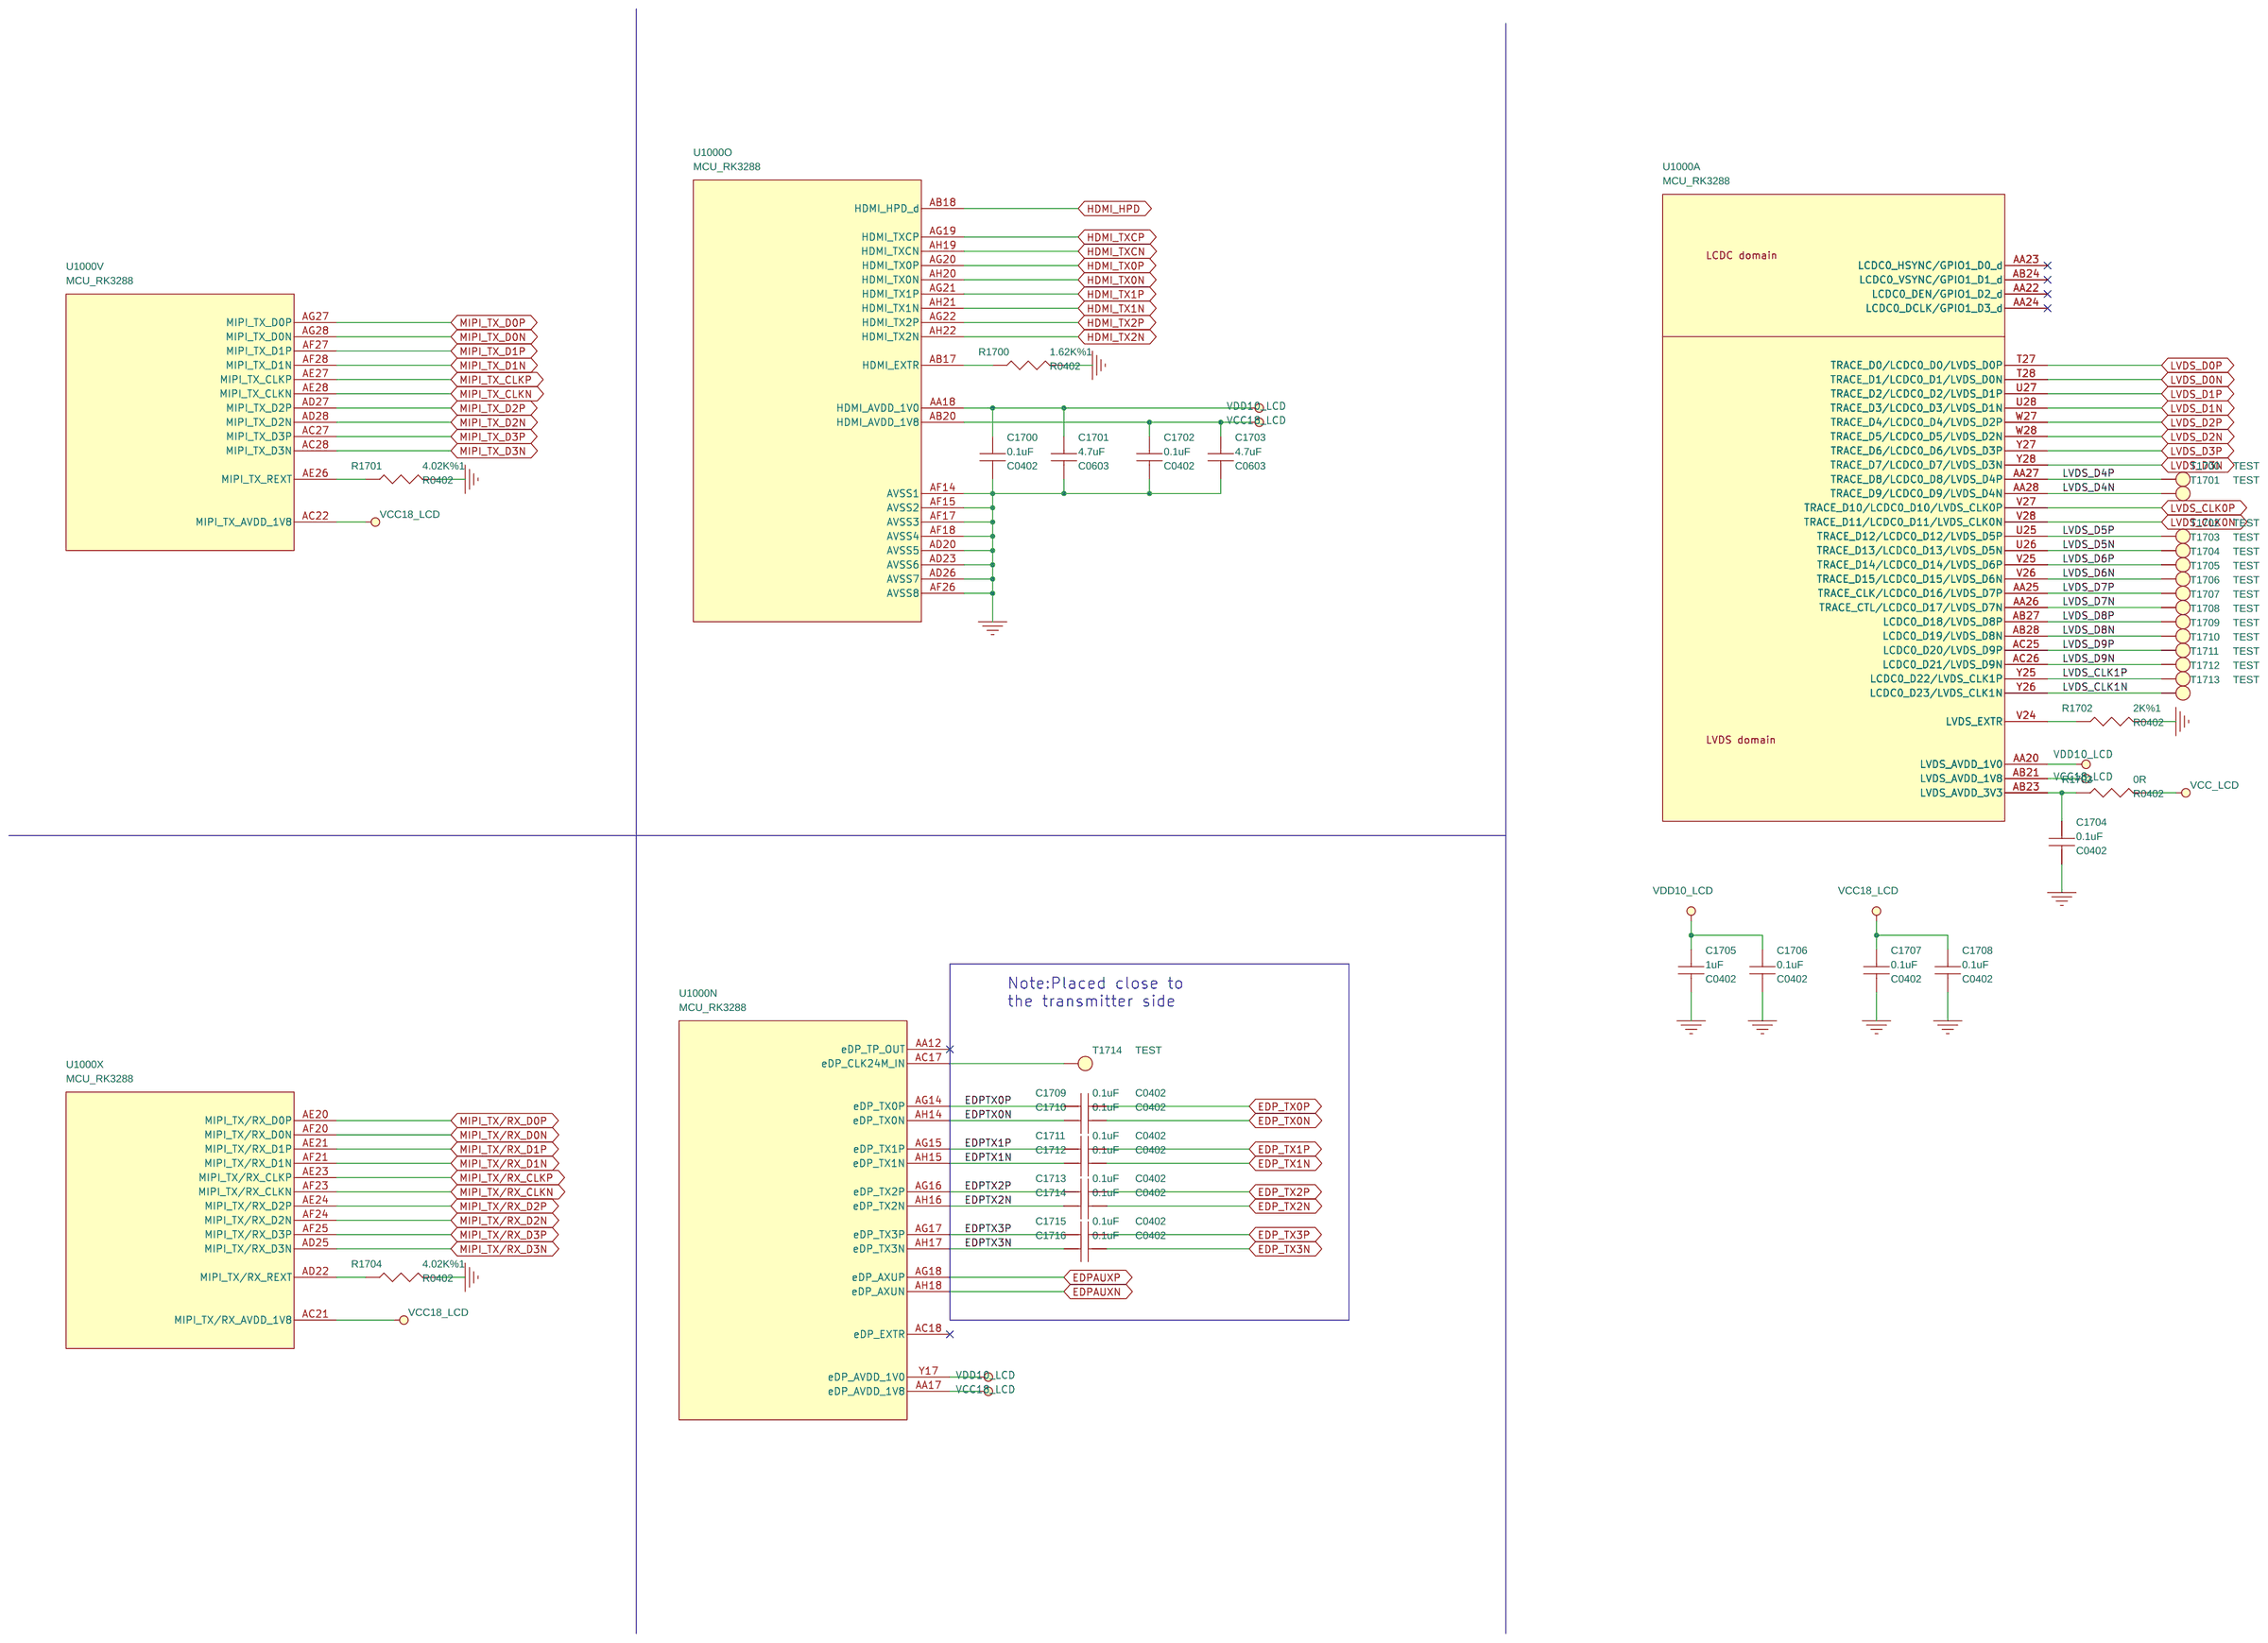
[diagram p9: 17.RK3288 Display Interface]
11 18.RK3288 GPIO: size A4; title: RK3288 GPIO; note: RK3288 GPIO
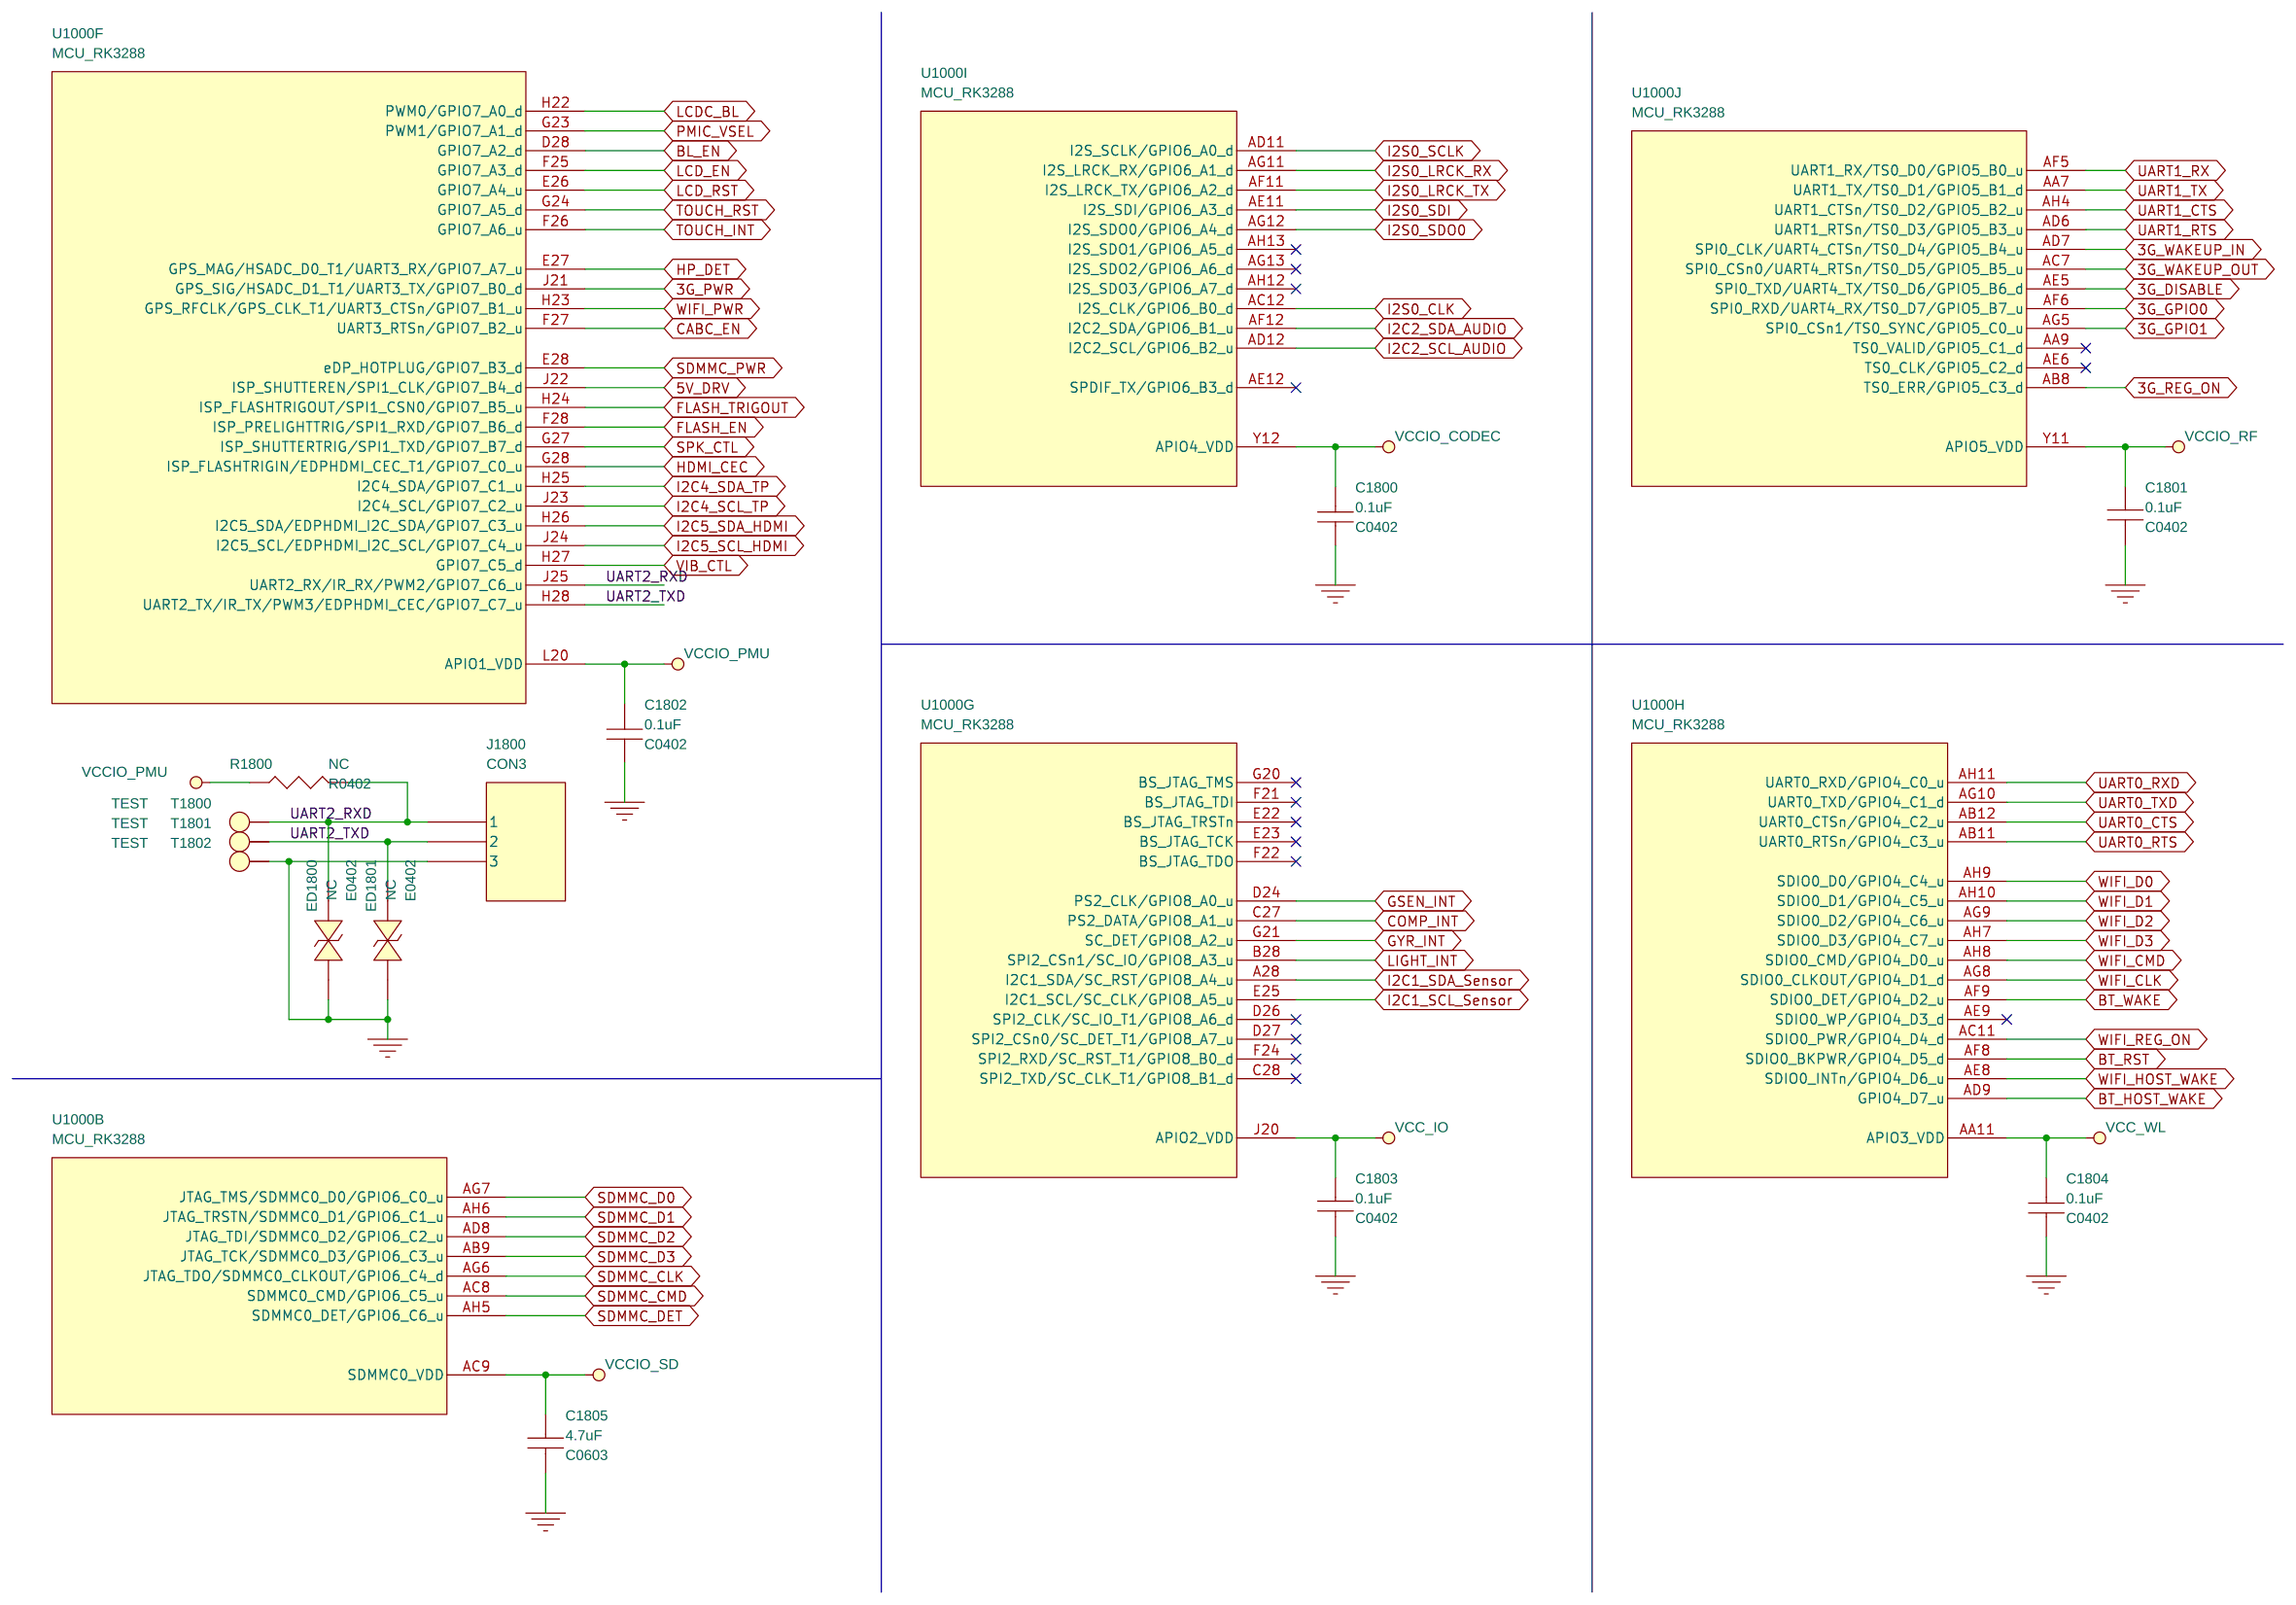
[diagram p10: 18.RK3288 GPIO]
12 20.USB Port: size A4; title: USB Port; note: USB Port
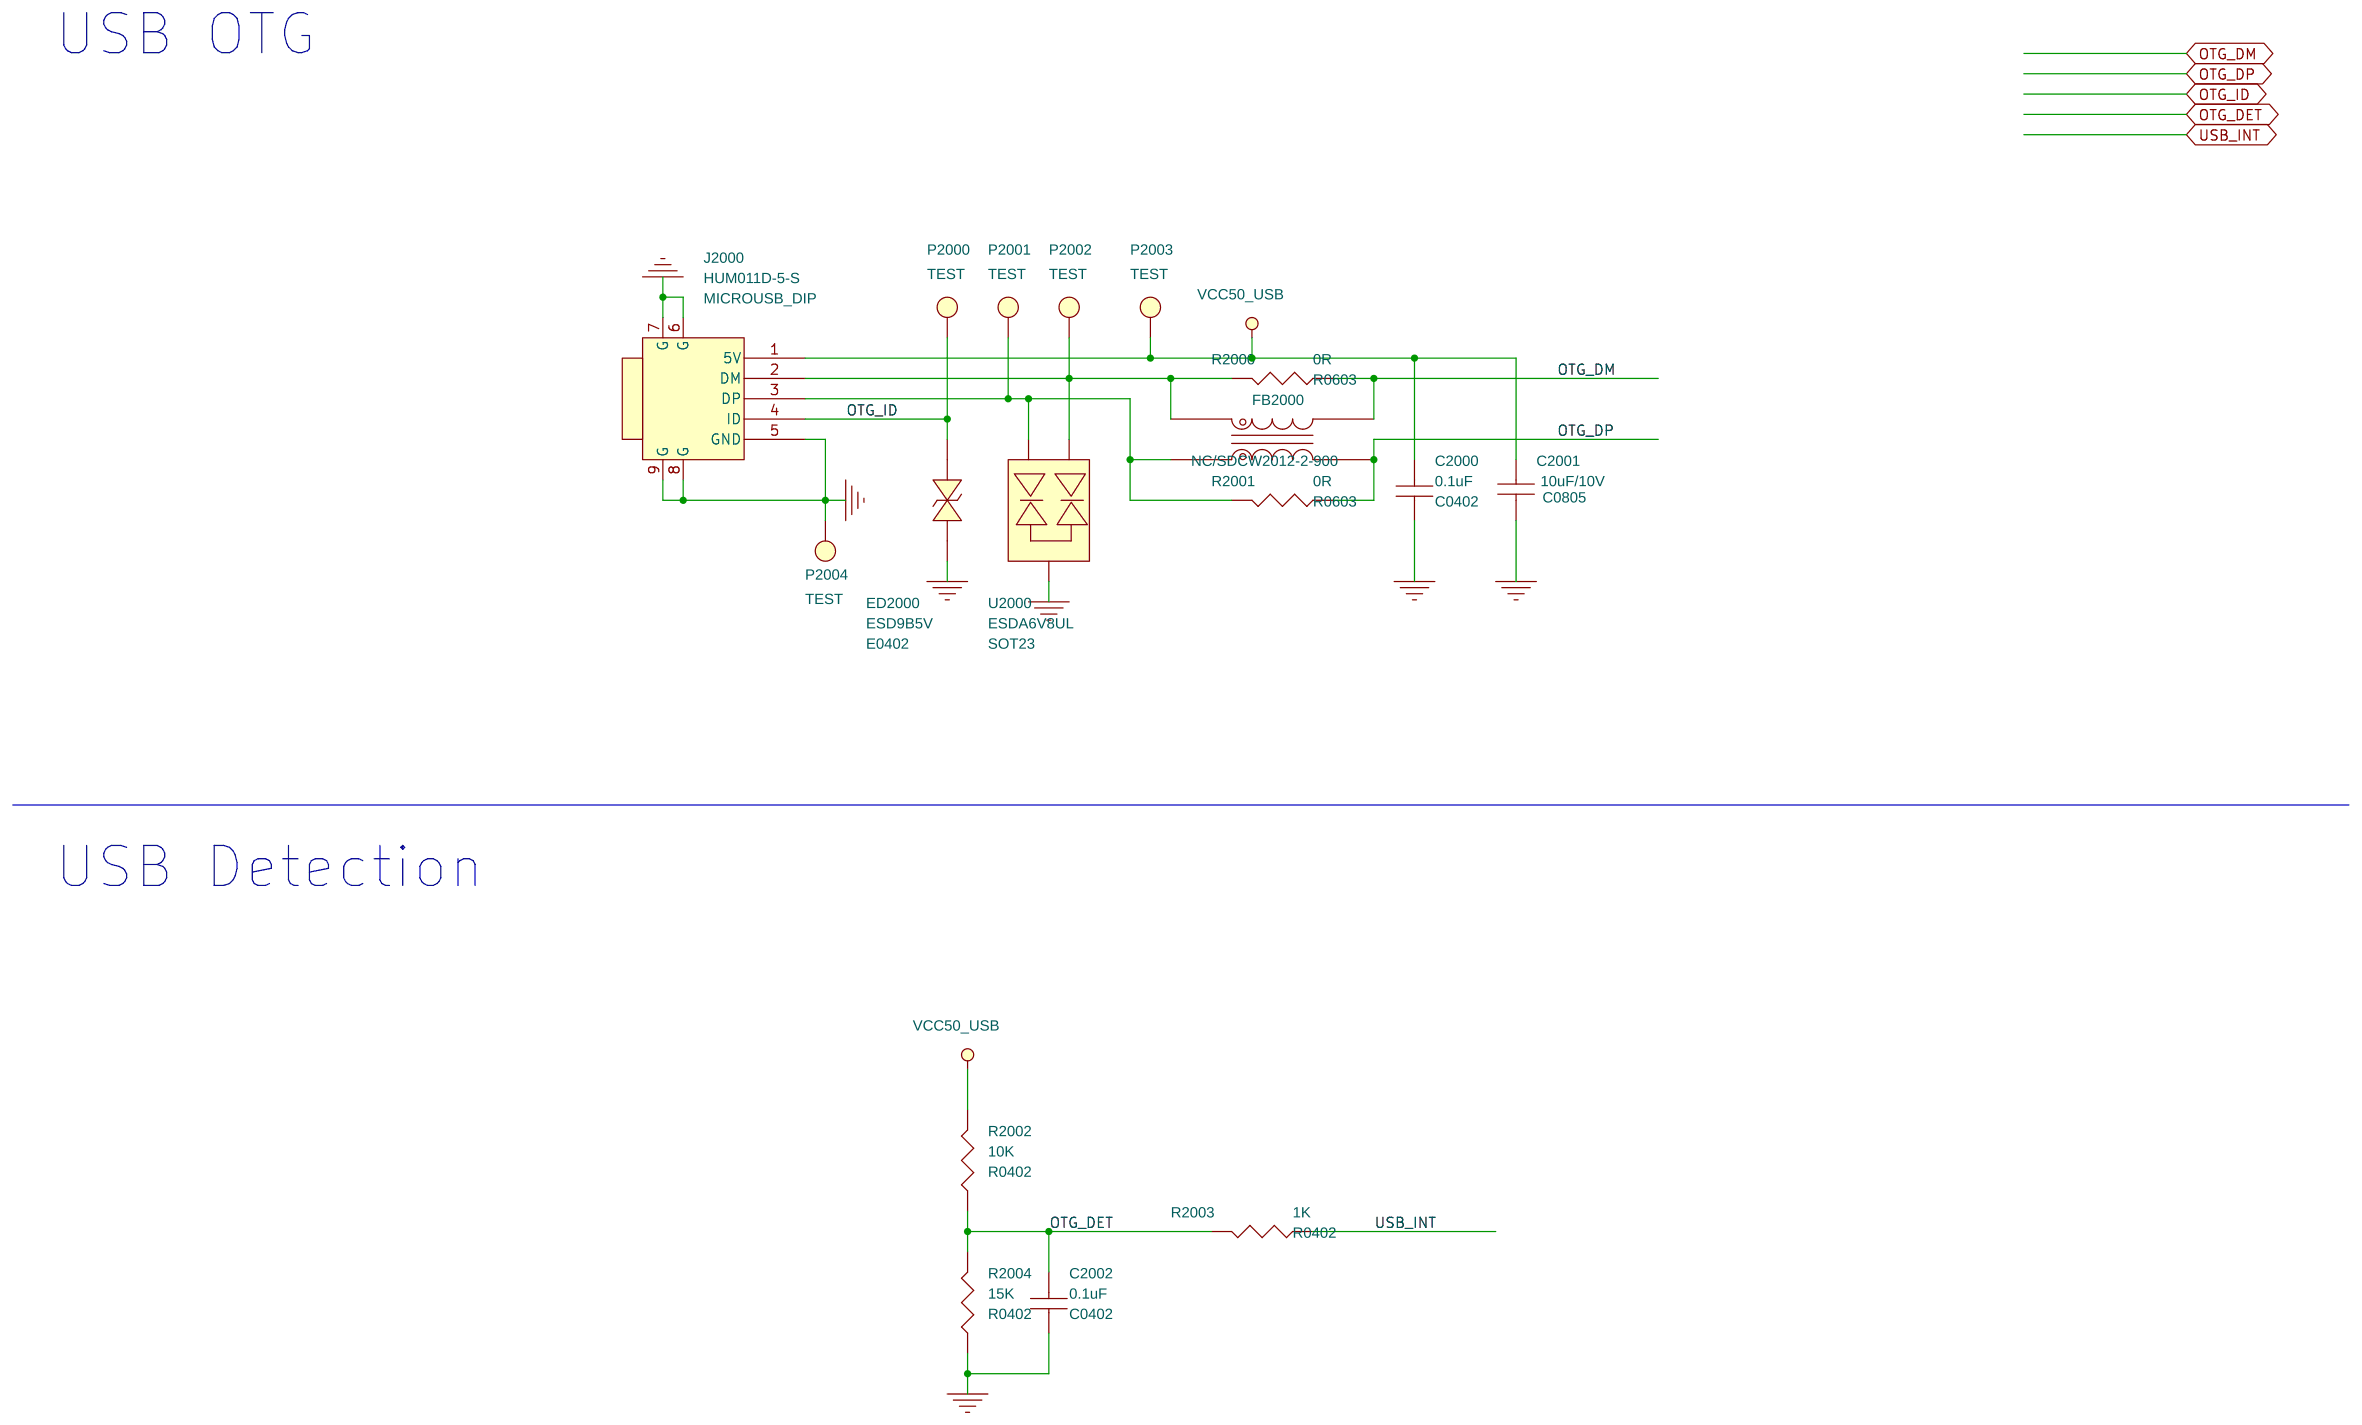
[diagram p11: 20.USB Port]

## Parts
sheet 10.RK3288 Power
C1000  10uF  [C0603]
C1001  0.1uF  [C0402]
C1002  0.1uF  [C0402]
C1003  1nF  [C0402]
C1004  NC/10uF  [C0603]
C1005  NC  [C0402]
C1006  0.1uF  [C0402]
C1007  22uF  [C0805]
C1008  22uF  [C0805]
C1009  22uF  [C0805]
C1010  22uF  [C0805]
C1011  22uF  [C0805]
C1012  22uF  [C0805]
C1013  22uF  [C0805]
C1014  10uF  [C0603]
C1015  1uF  [C0402]
C1016  0.1uF  [C0402]
C1017  0.1uF  [C0402]
C1018  1nF  [C0402]
C1019  22uF  [C0805]
C1020  22uF  [C0805]
C1021  10uF  [C0603]
C1022  10uF  [C0603]
C1023  1uF  [C0402]
C1024  0.1uF  [C0402]
C1025  0.1uF  [C0402]
C1026  1nF  [C0402]
sheet 11.RK3288 PMU Controler
C1100  0.1uF  [C0402]
C1101  8pF  [C0402]
C1102  8pF  [C0402]
C1103  0.1uF  [C0402]
C1104  0.1uF  [C0402]
C1105  0.1uF  [C0402]
R1100  1M  [R0402]
R1101  33R  [R0402]
R1102  NC  [R0402]
R1103  510R  [R0402]
Y1100  24M-30ppm  [CRY-D3225]
sheet 12.RK3288 DDR Controler
C1200  10uF  [C0603]
C1201  0.1uF  [C0402]
C1202  1nF  [C0402]
C1203  0.1uF  [C0402]
C1204  1nF  [C0402]
C1205  1uF  [C0402]
C1206  0.1uF  [C0402]
C1207  1nF  [C0402]
C1208  0.1uF  [C0402]
C1209  1nF  [C0402]
C1210  0.1uF  [C0402]
C1211  0.1uF  [C0402]
C1212  0.1uF  [C0402]
C1213  1nF  [C0402]
C1214  0.1uF  [C0402]
C1215  1nF  [C0402]
R1200  240R%1  [R0402]
R1201  240R%1  [R0402]
R1204  120K  [R0402]
R1205  120K  [R0402]
R1206  120K  [R0402]
R1207  120K  [R0402]
R1208  1K%1  [R0402]
R1209  1K%1  [R0402]
R1210  1K%1  [R0402]
R1211  1K%1  [R0402]
R1212  10K%1  [R0402]
R1213  10K%1  [R0402]
R1214  10K%1  [R0402]
R1215  10K%1  [R0402]
sheet 13.RK3288 Flash Controler
C1300  0.1uF  [C0402]
C1301  0.1uF  [C0402]
R1300  0R/NC  [R0402]
U1000  MCU_RK3288  [BGA636_19x19]  (sections A,B,C,D,E,F,G,H,I,J,K,L,M,N,O,P,Q,R,T,U,V,W,X)
sheet 16.RK3288 DVP Interface
C1600  0.1uF  [C0402]
sheet 17.RK3288 Display Interface
C1700  0.1uF  [C0402]
C1701  4.7uF  [C0603]
C1702  0.1uF  [C0402]
C1703  4.7uF  [C0603]
C1704  0.1uF  [C0402]
C1705  1uF  [C0402]
C1706  0.1uF  [C0402]
C1707  0.1uF  [C0402]
C1708  0.1uF  [C0402]
C1709  0.1uF  [C0402]
C1710  0.1uF  [C0402]
C1711  0.1uF  [C0402]
C1712  0.1uF  [C0402]
C1713  0.1uF  [C0402]
C1714  0.1uF  [C0402]
C1715  0.1uF  [C0402]
C1716  0.1uF  [C0402]
R1700  1.62K%1  [R0402]
R1701  4.02K%1  [R0402]
R1702  2K%1  [R0402]
R1703  0R  [R0402]
R1704  4.02K%1  [R0402]
T1700  TEST  [T-0.7]
T1701  TEST  [T-0.7]
T1702  TEST  [T-0.7]
T1703  TEST  [T-0.7]
T1704  TEST  [T-0.7]
T1705  TEST  [T-0.7]
T1706  TEST  [T-0.7]
T1707  TEST  [T-0.7]
T1708  TEST  [T-0.7]
T1709  TEST  [T-0.7]
T1710  TEST  [T-0.7]
T1711  TEST  [T-0.7]
T1712  TEST  [T-0.7]
T1713  TEST  [T-0.7]
T1714  TEST  [T-0.7]
sheet 18.RK3288 GPIO
C1800  0.1uF  [C0402]
C1801  0.1uF  [C0402]
C1802  0.1uF  [C0402]
C1803  0.1uF  [C0402]
C1804  0.1uF  [C0402]
C1805  4.7uF  [C0603]
ED1800  NC  [E0402]
ED1801  NC  [E0402]
J1800  CON3  [UART-DEBUG]
R1800  NC  [R0402]
T1800  TEST  [T-0.7]
T1801  TEST  [T-0.7]
T1802  TEST  [T-0.7]
sheet 20.USB Port
C2000  0.1uF  [C0402]
C2001  10uF/10V  [C0805]
C2002  0.1uF  [C0402]
ED2000  ESD9B5V  [E0402]
FB2000  NC/SDCW2012-2-900  [L0603D]
J2000  HUM011D-5-S  [MICROUSB_DIP]
P2000  TEST  [T-0.7]
P2001  TEST  [T-0.7]
P2002  TEST  [T-0.7]
P2003  TEST  [T-0.7]
P2004  TEST  [T-0.7]
R2000  0R  [R0603]
R2001  0R  [R0603]
R2002  10K  [R0402]
R2003  1K  [R0402]
R2004  15K  [R0402]
U2000  ESDA6V8UL  [SOT23]

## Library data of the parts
C1000 C1022 = CAP_NP: CAP,MLCC,10uF,+/-10%,X5R,6.3V,SMD0805
C1001-C1005 C1013-C1021 C1023-C1026 C1101 C1102 C1200-C1215 C1801 C1803 C2001 C2002 = CAP_NP
C1006 C1700-C1716 C1800 C1802 C1804 C1805 = CAP_NP: CAP,MLCC,100nF,+/-10%,X7R,6.3V,SMD0402
C1007-C1012 = CAP_NP: CAP,MLCC,47uF,+/-10%,X5R,4V,SMD1210
C1100 C1103-C1105 C2000 = CAP_NP: 贴片电容; MARK: 106; ROOM: USB+5V
R1100-R1102 R2002-R2004 = RESISTOR_1
R1103 = RESISTOR_0: RES,thick film,100KOhm,+/-5%,1/16W,SMD0402; MARK: 51K
Y1100 = CRYSTAL-4_1
R1200 R1201 R1204-R1215 = RESISTOR_0: 贴片电阻
C1300 C1301 = CAP_NP: RoHS CHIP CAP 0.1uF +10/-10% X7R
R1300 R2000 R2001 = RESISTOR_0
U1000 = MCU_RK3288
C1600 = CAP_NP: CAP,MLCC,1uF,+/-10%,X5R,6.3V,SMD0402
R1700-R1704 = RES_1B
P2000-P2004 T1700-T1714 T1800-T1802 = TESTPOINT1
ED1800 ED1801 = TVS: ESD Component,5V,30P,SMD,0402
J1800 = CON3
R1800 = RESISTOR: ROHS CHIP RES 10K 1/16W +/-5%
ED2000 = DIODE_BI-DIR_TRIG: ESD
FB2000 = INDUCTOR-COM: Chip common mode choke coil,90 ohm@100MHz,0.35 ohm/DCR,50V,330mA,-40°C~+ 85°C
J2000 = USB_MIN_4: USB
U2000 = ESDx2: ESD Protect for 2 high-speed I/O lines,±15kV air, ±8kV contact discharg,1.6pF,SMD,SOT23

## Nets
5V_DRV: U1000.J22(ISP_SHUTTEREN/SPI1_CLK/GPIO7_B4_d) ; also on sheet 13
GND: C1000.1 C1001.2 C1002.2 C1003.2 C1004.2 C1005.2 C1006.2 C1007.2 C1008.2 C1009.2 C1010.2 C1011.2 C1012.2 C1013.1 C1014.1 C1015.2 C1016.2 C1017.2 C1018.2 C1019.2 C1020.1 C1021.1 C1022.1 C1023.2 C1024.2 C1025.2 C1026.2 C1100.1 C1103.1 C1104.1 C1105.1 C1200.1 C1201.1 C1202.1 C1203.1 C1204.2 C1205.1 C1206.1 C1207.1 C1208.1 C1209.2 C1212.2 C1213.2 C1214.2 C1215.1 C1300.2 C1301.2 C1600.2 C1700.2 C1701.2 C1702.2 C1703.2 C1704.2 C1705.2 C1706.2 C1707.2 C1708.2 C1800.1 C1801.2 C1802.1 C1803.2 C1804.1 C1805.2 C2000.1 C2001.2 C2002.1 ED1800.2 ED1801.2 ED2000.2 J1800.3 J2000.5(GND) J2000.6(G) J2000.7(G) J2000.8(G) J2000.9(G) P2004.1 R1102.1 R1103.1 R1200.2 R1201.2 R1206.2 R1207.2 R1210.1 R1211.1 R1214.1 R1215.1 R1700.2 R1701.2 R1702.2 R1704.2 R2004.1 T1802.1 U1000.A21(VSS9) U1000.AC24(VSS11) U1000.AD20(AVSS5) U1000.AD23(AVSS6) U1000.AD26(AVSS7) U1000.AF14(AVSS1) U1000.AF15(AVSS2) U1000.AF17(AVSS3) U1000.AF18(AVSS4) U1000.AF26(AVSS8) U1000.C3(VSS1) U1000.D6(VSS2) U1000.D9(VSS3) U1000.D12(VSS4) U1000.D15(VSS5) U1000.D18(VSS6) U1000.E20(VSS7) U1000.F4(VSS12) U1000.J4(VSS13) U1000.J9(VSS14) U1000.J17(VSS16) U1000.J18(VSS28) U1000.K10(VSS18) U1000.K11(VSS19) U1000.K12(VSS20) U1000.K13(VSS21) U1000.K14(VSS22) U1000.K15(VSS23) U1000.K16(VSS24) U1000.K17(VSS25) U1000.K18(VSS26) U1000.K19(VSS27) U1000.L10(VSS29) U1000.L11(VSS30) U1000.L13(VSS31) U1000.L14(VSS32) U1000.L15(VSS33) U1000.M4(VSS34) U1000.M10(VSS35) U1000.M11(VSS36) U1000.M13(VSS37) U1000.M14(VSS38) U1000.M26(TEST) U1000.N10(VSS40) U1000.N11(VSS41) U1000.N13(VSS42) U1000.N14(VSS43) U1000.N15(VSS44) U1000.P10(VSS45) U1000.P11(VSS46) U1000.P13(VSS47) U1000.P14(VSS48) U1000.P15(VSS49) U1000.P16(VSS50) U1000.P17(VSS51) U1000.P18(VSS52) U1000.P27(PLL_AVSS) U1000.R4(VSS53) U1000.R10(VSS54) U1000.R13(VSS55) U1000.R14(VSS61) U1000.R15(VSS71) U1000.R16(VSS56) U1000.R17(VSS57) U1000.R18(VSS58) U1000.R19(VSS59) U1000.T10(VSS60) U1000.T13(VSS62) U1000.T15(VSS64) U1000.T16(VSS65) U1000.T17(VSS66) U1000.T18(VSS67) U1000.T19(VSS68) U1000.U9(VSS15) U1000.U10(VSS70) U1000.U13(VSS72) U1000.U24(VSS8) U1000.V4(VSS73) U1000.V9(VSS69) U1000.V10(VSS74) U1000.V11(VSS75) U1000.V12(VSS76) U1000.V13(VSS77) U1000.W10(VSS17) U1000.W11(VSS78) U1000.W12(VSS79) U1000.W13(VSS80) U1000.W14(VSS81) U1000.W15(VSS82) U1000.W16(VSS83) U1000.W17(VSS84) U1000.W18(VSS85) U1000.W19(VSS86) U1000.Y18(VSS39) U1000.Y20(VSS63) U1000.Y24(VSS10) U2000.3 ; also on sheet 13 14 15 16 17 18 19 20 21 22 23 24 25 26 27 28 29 30 31 32 33 34 35 36 37 38 39 40 41 42 43 44 45 46 47 48
VCC18_DVP: C1600.1 U1000.U20(DVPIO_VDD) ; also on sheet 24 25 26
VCC18_LCD: C1702.1 C1703.1 C1707.1 C1708.1 U1000.AA17(eDP_AVDD_1V8) U1000.AB20(HDMI_AVDD_1V8) U1000.AB21(LVDS_AVDD_1V8) U1000.AC21(MIPI_TX/RX_AVDD_1V8) U1000.AC22(MIPI_TX_AVDD_1V8) ; also on sheet 13 14 29
VCC50_USB: C2000.2 C2001.1 J2000.1(5V) P2003.1 R2002.2 ; also on sheet 13 14
VCC_DDR: C1203.2 C1208.2 C1210.1 C1211.1 R1212.1 R1213.1 U1000.H14(DDR0_VDDAO) U1000.P8(DDR1_VDDAO) ; also on sheet 13 14 15 16 17 18 19 20
VCC_DDRC: C1200.2 C1201.2 C1202.2 C1205.2 C1206.2 C1207.2 R1208.1 R1209.1 U1000.H9(DDR0_VDD1) U1000.J8(DDR1_VDD1) U1000.J11(DDR0_VDD2) U1000.J12(DDR0_VDD3) U1000.J14(DDR0_VDD4) U1000.J15(DDR0_VDD5) U1000.L9(DDR1_VDD2) U1000.M9(DDR1_VDD3) U1000.P9(DDR1_VDD4) U1000.R9(DDR1_VDD5) ; also on sheet 15 16 17 18 19 20
VCC_EFUSE: R1103.2 U1000.P19(EFUSE_VQPS) ; also on sheet 42
VCC_IO: C1803.1 U1000.J20(APIO2_VDD) ; also on sheet 13 14 21 22 23 24 31 32 33 34 35 41 42 43
VCC_LCD: C1006.1 R1703.2 U1000.V20(LCDC_VDD) ; also on sheet 13 14 27 28 29 30
VCC_WL: C1804.2 U1000.AA11(APIO3_VDD) ; also on sheet 13 14 44 47 48
VCCIO_CODEC: C1800.2 U1000.Y12(APIO4_VDD) ; also on sheet 32 33 34 35
VCCIO_FLASH: C1300.1 C1301.1 R1300.1 U1000.V8(FLASH1_VDD) U1000.Y9(FLASH0_VDD) ; also on sheet 21 22 23
VCCIO_PMU: C1105.2 C1802.2 R1800.1 U1000.L20(APIO1_VDD) U1000.P20(PUMIO_VDD) ; also on sheet 13 14 17 18 19 20 24 33 34 35 41 43 46
VCCIO_RF: C1801.1 U1000.Y11(APIO5_VDD) ; also on sheet 31 32
VCCIO_SD: C1805.1 U1000.AC9(SDMMC0_VDD) ; also on sheet 13 14 40
VDD10_LCD: C1700.1 C1701.1 C1705.1 C1706.1 U1000.AA18(HDMI_AVDD_1V0) U1000.AA20(LVDS_AVDD_1V0) U1000.Y17(eDP_AVDD_1V0) ; also on sheet 13 14
VDD_10: C1103.2 C1104.2 U1000.M20(PMU_VDD_1V0) U1000.P28(PLL_AVDD_1V0) ; also on sheet 13 14 46
VDD_CPU: C1007.1 C1008.1 C1009.1 C1010.1 C1011.1 C1012.1 C1013.2 C1014.2 C1015.1 C1016.1 C1017.1 C1018.1 U1000.U14(CPU_VDD1) U1000.U15(CPU_VDD2) U1000.U16(CPU_VDD3) U1000.U17(CPU_VDD4) U1000.U18(CPU_VDD5) U1000.U19(CPU_VDD6) U1000.V14(CPU_VDD7) U1000.V15(CPU_VDD8) U1000.V16(CPU_VDD9) U1000.V17(CPU_VDD10) U1000.V18(CPU_VDD11) U1000.V19(CPU_VDD12) ; also on sheet 13 14
VDD_CPU_FB: U1000.T14(CPU_VDD_COM) ; also on sheet 13 14
VDD_GPU: C1019.1 C1020.2 C1021.2 C1022.2 C1023.1 C1024.1 C1025.1 C1026.1 U1000.L16(GPU_VDD1) U1000.L17(GPU_VDD2) U1000.L18(GPU_VDD3) U1000.L19(GPU_VDD4) U1000.M16(GPU_VDD5) U1000.M17(GPU_VDD6) U1000.M18(GPU_VDD7) U1000.M19(GPU_VDD8) U1000.N16(GPU_VDD9) U1000.N17(GPU_VDD10) U1000.N18(GPU_VDD11) U1000.N19(GPU_VDD12) ; also on sheet 13 14
VDD_GPU_FB: U1000.M15(GPU_VDD_COM) ; also on sheet 13 14
VDD_LOG: C1000.2 C1001.1 C1002.1 C1003.1 C1004.1 C1005.1 U1000.L12(LOGIC_VDD1) U1000.M12(LOGIC_VDD2) U1000.N12(LOGIC_VDD3) U1000.P12(LOGIC_VDD4) U1000.R11(LOGIC_VDD8) U1000.R12(LOGIC_VDD5) U1000.T11(LOGIC_VDD9) U1000.T12(LOGIC_VDD6) U1000.U11(LOGIC_VDD10) U1000.U12(LOGIC_VDD7) ; also on sheet 13 14
3G_DISABLE: U1000.AE5(SPI0_TXD/UART4_TX/TS0_D6/GPIO5_B6_d) ; also on sheet 31
3G_GPIO0: U1000.AF6(SPI0_RXD/UART4_RX/TS0_D7/GPIO5_B7_u) ; also on sheet 31 32
3G_GPIO1: U1000.AG5(SPI0_CSn1/TS0_SYNC/GPIO5_C0_u) ; also on sheet 32
3G_PWR: U1000.J21(GPS_SIG/HSADC_D1_T1/UART3_TX/GPIO7_B0_d) ; also on sheet 13 14 31 32
3G_REG_ON: U1000.AB8(TS0_ERR/GPIO5_C3_d) ; also on sheet 31
3G_WAKEUP_IN: U1000.AD7(SPI0_CLK/UART4_CTSn/TS0_D4/GPIO5_B4_u) ; also on sheet 31 32
3G_WAKEUP_OUT: U1000.AC7(SPI0_CSn0/UART4_RTSn/TS0_D5/GPIO5_B5_u) ; also on sheet 31 32
BL_EN: U1000.D28(GPIO7_A2_d) ; also on sheet 14 27 28 29 30
BT_HOST_WAKE: U1000.AD9(GPIO4_D7_u) ; also on sheet 44 47 48
BT_RST: U1000.AF8(SDIO0_BKPWR/GPIO4_D5_d) ; also on sheet 44 47 48
BT_WAKE: U1000.AF9(SDIO0_DET/GPIO4_D2_u) ; also on sheet 44 47 48
CABC_EN: U1000.F27(UART3_RTSn/GPIO7_B2_u) ; also on sheet 28 30
CHG_DET: U1000.L25(PMUGPIO0_B1_u) ; also on sheet 14
CHG_INT: U1000.L23(PMUGPIO0_A7_u) ; also on sheet 14
CIF_CLKI: U1000.V22(HOST_WKACK/GPS_CLK/TS_CLKOUT/CIF_CLKIN/GPIO2_B2_d) ; also on sheet 26
CIF_CLKO: U1000.R22(HOST_WKREQ/TS_FAIL/CIF_CLKOUT/GPIO2_B3_d) ; also on sheet 25 26
CIF_D0: U1000.R27(CIF_D0/GPIO2_B4_d) ; also on sheet 26
CIF_D1: U1000.R26(CIF_D1/GPIO2_B5_d) ; also on sheet 26
CIF_D2: U1000.Y23(HOST_D0/TS_D0/CIF_D2/GPIO2_A0_d) ; also on sheet 26
CIF_D3: U1000.Y21(HOST_D1/TS_D1/CIF_D3/GPIO2_A1_d) ; also on sheet 26
CIF_D4: U1000.Y22(HOST_D2/TS_D2/CIF_D4/GPIO2_A2_d) ; also on sheet 26
CIF_D5: U1000.V21(HOST_D3/TS_D3/CIF_D5/GPIO2_A3_d) ; also on sheet 26
CIF_D6: U1000.U22(HOST_CKINP/TS_D4/CIF_D6/GPIO2_A4_d) ; also on sheet 26
CIF_D7: U1000.U21(HOST_CKINN/TS_D5/CIF_D7/GPIO2_A5_d) ; also on sheet 26
CIF_HREF: U1000.R28(HOST_D7/TS_VALID/CIF_HREF/GPIO2_B1_d) ; also on sheet 26
CIF_PDN0: U1000.R24(CIF_D10/GPIO2_B6_d) ; also on sheet 26
CIF_PDN1: U1000.R21(CIF_D11/GPIO2_B7_d) ; also on sheet 25 26
CIF_VSYNC: U1000.R25(HOST_D6/TS_SYNC/CIF_VSYNC/GPIO2_B0_d) ; also on sheet 26
COMP_INT: U1000.C27(PS2_DATA/GPIO8_A1_u) ; also on sheet 43
DC_DET: U1000.L24(PMUGPIO0_B0_u) ; also on sheet 13 14
DDR0_A0: U1000.B10(DDR0_A0) ; also on sheet 15 16 17 18 19 20
DDR0_A1: U1000.C11(DDR0_A1) ; also on sheet 15 16 17 18 19 20
DDR0_A2: U1000.A10(DDR0_A2) ; also on sheet 15 16 17 18 19 20
DDR0_A3: U1000.E12(DDR0_A3) ; also on sheet 15 16 17 18 19 20
DDR0_A4: U1000.F12(DDR0_A4) ; also on sheet 15 16 17 18 19 20
DDR0_A5: U1000.B12(DDR0_A5) ; also on sheet 15 16 17 18 19 20
DDR0_A6: U1000.C12(DDR0_A6) ; also on sheet 15 16 17 18 19 20
DDR0_A7: U1000.A12(DDR0_A7) ; also on sheet 15 16 17 18 19 20
DDR0_A8: U1000.B13(DDR0_A8) ; also on sheet 15 16 17 18 19 20
DDR0_A9: U1000.A14(DDR0_A9) ; also on sheet 15 16 17 18 19 20
DDR0_A10: U1000.A13(DDR0_A10) ; also on sheet 15 16
DDR0_A11: U1000.D14(DDR0_A11) ; also on sheet 15 16
DDR0_A12: U1000.F14(DDR0_A12) ; also on sheet 15 16
DDR0_A13: U1000.C14(DDR0_A13) ; also on sheet 15 16
DDR0_A14: U1000.B14(DDR0_A14) ; also on sheet 15 16
DDR0_A15: U1000.C15(DDR0_A15) ; also on sheet 15
DDR0_BA0: U1000.D8(DDR0_BA0) ; also on sheet 15 16
DDR0_BA1: U1000.A9(DDR0_BA1) ; also on sheet 15 16
DDR0_BA2: U1000.E11(DDR0_BA2) ; also on sheet 15 16
DDR0_CASN: U1000.A8(DDR0_CASn) ; also on sheet 15 16
DDR0_CKE0: U1000.C9(DDR0_CKE0) ; also on sheet 15 16 17 18 19 20
DDR0_CKE1: U1000.C8(DDR0_CKE1) ; also on sheet 15 17 18 19 20
DDR0_CLK: U1000.B11(DDR0_CLK) ; also on sheet 15 16 17 18 19 20
DDR0_CLKN: U1000.A11(DDR0_CLKn) ; also on sheet 15 16 17 18 19 20
DDR0_CS0N: U1000.B8(DDR0_CSn0) ; also on sheet 15 16 17 18 19 20
DDR0_CS1N: U1000.F11(DDR0_CSn1) ; also on sheet 15 17 18 19 20
DDR0_D0: U1000.B19(DDR0_DQ0) ; also on sheet 15 16 17 18 19 20
DDR0_D1: U1000.C18(DDR0_DQ1) ; also on sheet 15 16 17 18 19 20
DDR0_D2: U1000.F17(DDR0_DQ2) ; also on sheet 15 16 17 18 19 20
DDR0_D3: U1000.F18(DDR0_DQ3) ; also on sheet 15 16 17 18 19 20
DDR0_D4: U1000.A19(DDR0_DQ4) ; also on sheet 15 16 17 18 19 20
DDR0_D5: U1000.E18(DDR0_DQ5) ; also on sheet 15 16 17 18 19 20
DDR0_D6: U1000.C20(DDR0_DQ6) ; also on sheet 15 16 17 18 19 20
DDR0_D7: U1000.D20(DDR0_DQ7) ; also on sheet 15 16 17 18 19 20
DDR0_D8: U1000.B5(DDR0_DQ8) ; also on sheet 15 16 17 18 19 20
DDR0_D9: U1000.A5(DDR0_DQ9) ; also on sheet 15 16 17 18 19 20
DDR0_D10: U1000.A3(DDR0_DQ10) ; also on sheet 15 16 17 18 19 20
DDR0_D11: U1000.C6(DDR0_DQ11) ; also on sheet 15 16 17 18 19 20
DDR0_D12: U1000.E8(DDR0_DQ12) ; also on sheet 15 16 17 18 19 20
DDR0_D13: U1000.A6(DDR0_DQ13) ; also on sheet 15 16 17 18 19 20
DDR0_D14: U1000.B6(DDR0_DQ14) ; also on sheet 15 16 17 18 19 20
DDR0_D15: U1000.F8(DDR0_DQ15) ; also on sheet 15 16 17 18 19 20
DDR0_D16: U1000.B15(DDR0_DQ16) ; also on sheet 15 16 17 18 19 20
DDR0_D17: U1000.A16(DDR0_DQ17) ; also on sheet 15 16 17 18 19 20
DDR0_D18: U1000.F15(DDR0_DQ18) ; also on sheet 15 16 17 18 19 20
DDR0_D19: U1000.B16(DDR0_DQ19) ; also on sheet 15 16 17 18 19 20
DDR0_D20: U1000.D17(DDR0_DQ20) ; also on sheet 15 16 17 18 19 20
DDR0_D21: U1000.B18(DDR0_DQ21) ; also on sheet 15 16 17 18 19 20
DDR0_D22: U1000.C17(DDR0_DQ22) ; also on sheet 15 16 17 18 19 20
DDR0_D23: U1000.A18(DDR0_DQ23) ; also on sheet 15 16 17 18 19 20
DDR0_D24: U1000.A2(DDR0_DQ24) ; also on sheet 15 16 17 18 19 20
DDR0_D25: U1000.A1(DDR0_DQ25) ; also on sheet 15 16 17 18 19 20
DDR0_D26: U1000.D5(DDR0_DQ26) ; also on sheet 15 16 17 18 19 20
DDR0_D27: U1000.E6(DDR0_DQ27) ; also on sheet 15 16 17 18 19 20
DDR0_D28: U1000.C5(DDR0_DQ28) ; also on sheet 15 16 17 18 19 20
DDR0_D29: U1000.F7(DDR0_DQ29) ; also on sheet 15 16 17 18 19 20
DDR0_D30: U1000.C4(DDR0_DQ30) ; also on sheet 15 16 17 18 19 20
DDR0_D31: U1000.E7(DDR0_DQ31) ; also on sheet 15 16 17 18 19 20
DDR0_DM0: U1000.E17(DDR0_DM0) ; also on sheet 15 16 17 18 19 20
DDR0_DM1: U1000.F9(DDR0_DM1) ; also on sheet 15 16 17 18 19 20
DDR0_DM2: U1000.A15(DDR0_DM2) ; also on sheet 15 16 17 18 19 20
DDR0_DM3: U1000.B3(DDR0_DM3) ; also on sheet 15 16 17 18 19 20
DDR0_DQS0M: U1000.B20(DDR0_DQS0n) ; also on sheet 15 16 17 18 19 20
DDR0_DQS0P: U1000.A20(DDR0_DQS0) ; also on sheet 15 16 17 18 19 20
DDR0_DQS1M: U1000.A7(DDR0_DQS1n) ; also on sheet 15 16 17 18 19 20
DDR0_DQS1P: U1000.B7(DDR0_DQS1) ; also on sheet 15 16 17 18 19 20
DDR0_DQS2M: U1000.A17(DDR0_DQS2n) ; also on sheet 15 16 17 18 19 20
DDR0_DQS2P: U1000.B17(DDR0_DQS2) ; also on sheet 15 16 17 18 19 20
DDR0_DQS3M: U1000.A4(DDR0_DQS3n) ; also on sheet 15 16 17 18 19 20
DDR0_DQS3P: U1000.B4(DDR0_DQS3) ; also on sheet 15 16 17 18 19 20
DDR0_ODT0: U1000.E14(DDR0_ODT0) ; also on sheet 15 16 20
DDR0_ODT1: U1000.E15(DDR0_ODT1) ; also on sheet 15
DDR0_RASN: U1000.D11(DDR0_RASn) ; also on sheet 15 16
DDR0_RETLE: R1204.1 R1206.1 U1000.G8(DDR0_RETLE)
DDR0_RST: U1000.E9(DDR0_RESET) ; also on sheet 15 16
DDR0_WEN: U1000.B9(DDR0_WEn) ; also on sheet 15 16
DDR1_A0: U1000.L3(DDR1_A0) ; also on sheet 15 16 17 18 19 20
DDR1_A1: U1000.K2(DDR1_A1) ; also on sheet 15 16 17 18 19 20
DDR1_A2: U1000.K1(DDR1_A2) ; also on sheet 15 16 17 18 19 20
DDR1_A3: U1000.M5(DDR1_A3) ; also on sheet 15 16 17 18 19 20
DDR1_A4: U1000.M6(DDR1_A4) ; also on sheet 15 16 17 18 19 20
DDR1_A5: U1000.M2(DDR1_A5) ; also on sheet 15 16 17 18 19 20
DDR1_A6: U1000.M1(DDR1_A6) ; also on sheet 15 16 17 18 19 20
DDR1_A7: U1000.M3(DDR1_A7) ; also on sheet 15 16 17 18 19 20
DDR1_A8: U1000.N1(DDR1_A8) ; also on sheet 15 16 17 18 19 20
DDR1_A9: U1000.P1(DDR1_A9) ; also on sheet 15 16 17 18 19 20
DDR1_A10: U1000.N2(DDR1_A10) ; also on sheet 15 16
DDR1_A11: U1000.P4(DDR1_A11) ; also on sheet 15 16
DDR1_A12: U1000.P6(DDR1_A12) ; also on sheet 15 16
DDR1_A13: U1000.P3(DDR1_A13) ; also on sheet 15 16
DDR1_A14: U1000.P2(DDR1_A14) ; also on sheet 15 16
DDR1_A15: U1000.R1(DDR1_A15) ; also on sheet 15
DDR1_BA0: U1000.L4(DDR1_BA0) ; also on sheet 15 16
DDR1_BA1: U1000.J1(DDR1_BA1) ; also on sheet 15 16
DDR1_BA2: U1000.L5(DDR1_BA2) ; also on sheet 15 16
DDR1_CASN: U1000.H1(DDR1_CASn) ; also on sheet 15 16
DDR1_CKE0: U1000.F1(DDR1_CKE0) ; also on sheet 15 16 17 18 19 20
DDR1_CKE1: U1000.H3(DDR1_CKE1) ; also on sheet 15 17 18 19 20
DDR1_CLK: U1000.L2(DDR1_CLK) ; also on sheet 15 16 17 18 19 20
DDR1_CLKN: U1000.L1(DDR1_CLKn) ; also on sheet 15 16 17 18 19 20
DDR1_CS0N: U1000.H2(DDR1_CSn0) ; also on sheet 15 16 17 18 19 20
DDR1_CS1N: U1000.J3(DDR1_CSn1) ; also on sheet 15 17 18 19 20
DDR1_D0: U1000.W2(DDR1_DQ0) ; also on sheet 15 16 17 18 19 20
DDR1_D1: U1000.V3(DDR1_DQ1) ; also on sheet 15 16 17 18 19 20
DDR1_D2: U1000.Y1(DDR1_DQ2) ; also on sheet 15 16 17 18 19 20
DDR1_D3: U1000.U6(DDR1_DQ3) ; also on sheet 15 16 17 18 19 20
DDR1_D4: U1000.W1(DDR1_DQ4) ; also on sheet 15 16 17 18 19 20
DDR1_D5: U1000.Y2(DDR1_DQ5) ; also on sheet 15 16 17 18 19 20
DDR1_D6: U1000.V5(DDR1_DQ6) ; also on sheet 15 16 17 18 19 20
DDR1_D7: U1000.Y3(DDR1_DQ7) ; also on sheet 15 16 17 18 19 20
DDR1_D8: U1000.E2(DDR1_DQ8) ; also on sheet 15 16 17 18 19 20
DDR1_D9: U1000.E1(DDR1_DQ9) ; also on sheet 15 16 17 18 19 20
DDR1_D10: U1000.C1(DDR1_DQ10) ; also on sheet 15 16 17 18 19 20
DDR1_D11: U1000.F3(DDR1_DQ11) ; also on sheet 15 16 17 18 19 20
DDR1_D12: U1000.H5(DDR1_DQ12) ; also on sheet 15 16 17 18 19 20
DDR1_D13: U1000.H4(DDR1_DQ13) ; also on sheet 15 16 17 18 19 20
DDR1_D14: U1000.J5(DDR1_DQ14) ; also on sheet 15 16 17 18 19 20
DDR1_D15: U1000.J6(DDR1_DQ15) ; also on sheet 15 16 17 18 19 20
DDR1_D16: U1000.T2(DDR1_DQ16) ; also on sheet 15 16 17 18 19 20
DDR1_D17: U1000.R6(DDR1_DQ17) ; also on sheet 15 16 17 18 19 20
DDR1_D18: U1000.T1(DDR1_DQ18) ; also on sheet 15 16 17 18 19 20
DDR1_D19: U1000.R5(DDR1_DQ19) ; also on sheet 15 16 17 18 19 20
DDR1_D20: U1000.U4(DDR1_DQ20) ; also on sheet 15 16 17 18 19 20
DDR1_D21: U1000.V1(DDR1_DQ21) ; also on sheet 15 16 17 18 19 20
DDR1_D22: U1000.U3(DDR1_DQ22) ; also on sheet 15 16 17 18 19 20
DDR1_D23: U1000.V2(DDR1_DQ23) ; also on sheet 15 16 17 18 19 20
DDR1_D24: U1000.B1(DDR1_DQ24) ; also on sheet 15 16 17 18 19 20
DDR1_D25: U1000.B2(DDR1_DQ25) ; also on sheet 15 16 17 18 19 20
DDR1_D26: U1000.E4(DDR1_DQ26) ; also on sheet 15 16 17 18 19 20
DDR1_D27: U1000.G6(DDR1_DQ27) ; also on sheet 15 16 17 18 19 20
DDR1_D28: U1000.E3(DDR1_DQ28) ; also on sheet 15 16 17 18 19 20
DDR1_D29: U1000.F5(DDR1_DQ29) ; also on sheet 15 16 17 18 19 20
DDR1_D30: U1000.C2(DDR1_DQ30) ; also on sheet 15 16 17 18 19 20
DDR1_D31: U1000.H6(DDR1_DQ31) ; also on sheet 15 16 17 18 19 20
DDR1_DM0: U1000.U5(DDR1_DM0) ; also on sheet 15 16 17 18 19 20
DDR1_DM1: U1000.G5(DDR1_DM1) ; also on sheet 15 16 17 18 19 20
DDR1_DM2: U1000.R3(DDR1_DM2) ; also on sheet 15 16 17 18 19 20
DDR1_DM3: U1000.D3(DDR1_DM3) ; also on sheet 15 16 17 18 19 20
DDR1_DQS0M: U1000.AA1(DDR1_DQS0n) ; also on sheet 15 16 17 18 19 20
DDR1_DQS0P: U1000.AA2(DDR1_DQS0) ; also on sheet 15 16 17 18 19 20
DDR1_DQS1M: U1000.G1(DDR1_DQS1n) ; also on sheet 15 16 17 18 19 20
DDR1_DQS1P: U1000.G2(DDR1_DQS1) ; also on sheet 15 16 17 18 19 20
DDR1_DQS2M: U1000.U1(DDR1_DQS2n) ; also on sheet 15 16 17 18 19 20
DDR1_DQS2P: U1000.U2(DDR1_DQS2) ; also on sheet 15 16 17 18 19 20
DDR1_DQS3M: U1000.D1(DDR1_DQS3n) ; also on sheet 15 16 17 18 19 20
DDR1_DQS3P: U1000.D2(DDR1_DQS3) ; also on sheet 15 16 17 18 19 20
DDR1_ODT0: U1000.P5(DDR1_ODT0) ; also on sheet 15 16 20
DDR1_ODT1: U1000.R2(DDR1_ODT1) ; also on sheet 15
DDR1_RASN: U1000.L6(DDR1_RASn) ; also on sheet 15 16
DDR1_RETLE: R1205.1 R1207.1 U1000.H7(DDR1_RETLE)
DDR1_RST: U1000.F2(DDR1_RESET) ; also on sheet 15 16
DDR1_WEN: U1000.J2(DDR1_WEn) ; also on sheet 15 16
DDRIO_PWROFF: U1000.J27(DDRIO_PWROFF/PMUGPIO0_A1_d) ; also on sheet 15 16 17 18 19 20
DDRIO_RETEN: R1204.2 R1205.2 U1000.J26(DDRIO_RETEN/PMUGPIO0_A2_u)
DVP_PWR: U1000.M23(TEST_CLKO/CLK_27M_T1/PMUGPIO0_C1_d) ; also on sheet 24
EDP_TX0N: C1710.2 ; also on sheet 27
EDP_TX0P: C1709.2 ; also on sheet 27
EDP_TX1N: C1712.2 ; also on sheet 27
EDP_TX1P: C1711.2 ; also on sheet 27
EDP_TX2N: C1714.2 ; also on sheet 27
EDP_TX2P: C1713.2 ; also on sheet 27
EDP_TX3N: C1716.2 ; also on sheet 27
EDP_TX3P: C1715.2 ; also on sheet 27
EDPAUXN: U1000.AH18(eDP_AXUN) ; also on sheet 27
EDPAUXP: U1000.AG18(eDP_AXUP) ; also on sheet 27
EDPTX0N: C1710.1 U1000.AH14(eDP_TX0N)
EDPTX0P: C1709.1 U1000.AG14(eDP_TX0P)
EDPTX1N: C1712.1 U1000.AH15(eDP_TX1N)
EDPTX1P: C1711.1 U1000.AG15(eDP_TX1P)
EDPTX2N: C1714.1 U1000.AH16(eDP_TX2N)
EDPTX2P: C1713.1 U1000.AG16(eDP_TX2P)
EDPTX3N: C1716.1 U1000.AH17(eDP_TX3N)
EDPTX3P: C1715.1 U1000.AG17(eDP_TX3P)
EFUSE_PWR: U1000.K27(EFUSE_PWREN/PMUGPIO0_A3_u) ; also on sheet 42
FLASH0_ALE: U1000.AF4(FLASH0_ALE/GPIO3_B3_d) ; also on sheet 22
FLASH0_CLE: U1000.AH3(FLASH0_CLE/GPIO3_B4_d) ; also on sheet 22
FLASH0_CS0: U1000.AC5(FLASH0_CSn0/GPIO3_B6_u) ; also on sheet 22
FLASH0_CS1: U1000.AD4(FLASH0_CSn1/GPIO3_B7_u) ; also on sheet 22
FLASH0_CS2/EMMC_CMD: U1000.AC4(FLASH0_CSn2/EMMC_CMD/GPIO3_C0_u) ; also on sheet 21 22 23
FLASH0_CS3/EMMC_RST: U1000.Y7(FLASH0_CSn3/EMMC_RSTNOUT/GPIO3_C1_u) ; also on sheet 22
FLASH0_D0: U1000.AE3(FLASH0_D0/EMMC_D0/GPIO3_A0_u) ; also on sheet 21 22 23
FLASH0_D1: U1000.AD3(FLASH0_D1/EMMC_D1/GPIO3_A1_u) ; also on sheet 21 22 23
FLASH0_D2: U1000.AF3(FLASH0_D2/EMMC_D2/GPIO3_A2_u) ; also on sheet 21 22 23
FLASH0_D3: U1000.AF1(FLASH0_D3/EMMC_D3/GPIO3_A3_u) ; also on sheet 21 22 23
FLASH0_D4: U1000.AF2(FLASH0_D4/EMMC_D4/GPIO3_A4_u) ; also on sheet 21 22
FLASH0_D5: U1000.AG3(FLASH0_D5/EMMC_D5/GPIO3_A5_u) ; also on sheet 21 22
FLASH0_D6: U1000.AG1(FLASH0_D6/EMMC_D6/GPIO3_A6_u) ; also on sheet 21 22
FLASH0_D7: U1000.AG2(FLASH0_D7/EMMC_D7/GPIO3_A7_u) ; also on sheet 21 22
FLASH0_DQS/EMMC_CLKO: U1000.AB6(FLASH0_DQS/EMMC_CLKOUT/GPIO3_C2_d) ; also on sheet 21 22 23
FLASH0_RDN: U1000.Y6(FLASH0_RDN/GPIO3_B2_u) ; also on sheet 22
FLASH0_RDY: U1000.AH2(FLASH0_RDY/GPIO3_B0_u) ; also on sheet 22
FLASH0_WP/EMMC_PWREN: U1000.AH1(FLASH0_WP/EMMC_PWREN/GPIO3_B1_d) ; also on sheet 21 22
FLASH0_WRN: U1000.AG4(FLASH0_WRN/GPIO3_B5_u) ; also on sheet 22
FLASH1_ALE: U1000.AE2(HOST_D9/MAC_CLK/FLASH0_CSn6/FLASH1_ALE/GPIO4_A3_u) ; also on sheet 22
FLASH1_CLE: U1000.AD2(HOST_D10/MAC_TXEN/FLASH0_CSn7/FLASH1_CLE/GPIO4_A4_u) ; also on sheet 22
FLASH1_CSn0: U1000.AB5(HOST_D12/MAC_RXCLK/SDIO1_CMD/FLASH1_CSn0/GPIO4_A6_u) ; also on sheet 22
FLASH1_CSn1: U1000.AA6(HOST_D13/MAC_CRS/SDIO1_CLKOUT/FLASH1_CSn1/GPIO4_A7_u) ; also on sheet 22
FLASH1_D0: U1000.Y4(HOST_D0/MAC_TXD2/SDIO1_D0/FLASH1_D0/GPIO3_D0_u) ; also on sheet 22
FLASH1_D1: U1000.V6(HOST_D1/MAC_TXD3/SDIO1_D1/FLASH1_D1/GPIO3_D1_u) ; also on sheet 22
FLASH1_D2: U1000.AB1(HOST_D2/MAC_RXD2/SDIO1_D2/FLASH1_D2/GPIO3_D2_u) ; also on sheet 22
FLASH1_D3: U1000.AC1(HOST_D3/MAC_RXD3/SDIO1_D3/FLASH1_D3/GPIO3_D3_u) ; also on sheet 22
FLASH1_D4: U1000.AD1(HOST_D4/MAC_TXD0/SDIO1_DET/FLASH1_D4/GPIO3_D4_u) ; also on sheet 22
FLASH1_D5: U1000.AB2(HOST_D5/MAC_TXD1/SDIO1_WRPRT/FLASH1_D5/GPIO3_D5_u) ; also on sheet 22
FLASH1_D6: U1000.AA3(HOST_D6/MAC_RXD0/SDIO1_BKPWR/FLASH1_D6/GPIO3_D6_u) ; also on sheet 22
FLASH1_D7: U1000.AA4(HOST_D7/MAC_RXD1/SDIO1_INTn/FLASH1_D7/GPIO3_D7_u) ; also on sheet 22
FLASH1_DQS: U1000.AA5(HOST_D14/MAC_COL/FLASH1_DQS/FLASH1_CSn3/GPIO4_B0_u) ; also on sheet 22
FLASH1_RDN: U1000.AE1(HOST_D8/MAC_RXER/FLASH0_CSn5/FLASH1_RDN/GPIO4_A2_u) ; also on sheet 22
FLASH1_RDY: U1000.AC3(HOST_CKOUTP/MAC_MDC/FLASH1_RDY/GPIO4_A0_u) ; also on sheet 22
FLASH1_WP: U1000.AC2(HOST_CKOUTN/MAC_RXDV/FLASH0_CSn4/FLASH1_WP/GPIO4_A1_u) ; also on sheet 22
FLASH1_WRN: U1000.Y5(HOST_D11/MAC_MDIO/FLASH1_WRN/GPIO4_A5_u) ; also on sheet 22
FLASH_EN: U1000.F28(ISP_PRELIGHTTRIG/SPI1_RXD/GPIO7_B6_d) ; also on sheet 24
FLASH_TRIGOUT: U1000.H24(ISP_FLASHTRIGOUT/SPI1_CSN0/GPIO7_B5_u) ; also on sheet 24
GSEN_INT: U1000.D24(PS2_CLK/GPIO8_A0_u) ; also on sheet 43
GYR_INT: U1000.G21(SC_DET/GPIO8_A2_u) ; also on sheet 43
HALL_INT: U1000.L22(PMUGPIO0_A6_u) ; also on sheet 43
HDMI_CEC: U1000.G28(ISP_FLASHTRIGIN/EDPHDMI_CEC_T1/GPIO7_C0_u) ; also on sheet 41
HDMI_HPD: U1000.AB18(HDMI_HPD_d) ; also on sheet 41
HDMI_TX0N: U1000.AH20(HDMI_TX0N) ; also on sheet 41
HDMI_TX0P: U1000.AG20(HDMI_TX0P) ; also on sheet 41
HDMI_TX1N: U1000.AH21(HDMI_TX1N) ; also on sheet 41
HDMI_TX1P: U1000.AG21(HDMI_TX1P) ; also on sheet 41
HDMI_TX2N: U1000.AH22(HDMI_TX2N) ; also on sheet 41
HDMI_TX2P: U1000.AG22(HDMI_TX2P) ; also on sheet 41
HDMI_TXCN: U1000.AH19(HDMI_TXCN) ; also on sheet 41
HDMI_TXCP: U1000.AG19(HDMI_TXCP) ; also on sheet 41
HP_DET: U1000.E27(GPS_MAG/HSADC_D0_T1/UART3_RX/GPIO7_A7_u) ; also on sheet 33 34 35
I2C0_SCL_PMIC: U1000.M21(I2C0_SCL/PMUGPIO0_C0_u) ; also on sheet 13 14
I2C0_SDA_PMIC: U1000.M25(I2C0_SDA/PMUGPIO0_B7_u) ; also on sheet 13 14
I2C1_SCL_Sensor: U1000.E25(I2C1_SCL/SC_CLK/GPIO8_A5_u) ; also on sheet 43
I2C1_SDA_Sensor: U1000.A28(I2C1_SDA/SC_RST/GPIO8_A4_u) ; also on sheet 43
I2C2_SCL_AUDIO: U1000.AD12(I2C2_SCL/GPIO6_B2_u) ; also on sheet 31 32 33 34 35
I2C2_SDA_AUDIO: U1000.AF12(I2C2_SDA/GPIO6_B1_u) ; also on sheet 31 32 33 34 35
I2C3_SCL_CAM: U1000.P22(I2C3_SCL/GPIO2_C0_u) ; also on sheet 25 26
I2C3_SDA_CAM: U1000.R23(I2C3_SDA/GPIO2_C1_u) ; also on sheet 25 26
I2C4_SCL_TP: U1000.J23(I2C4_SCL/GPIO7_C2_u) ; also on sheet 30 36 37 38 39
I2C4_SDA_TP: U1000.H25(I2C4_SDA/GPIO7_C1_u) ; also on sheet 30 36 37 38 39
I2C5_SCL_HDMI: U1000.J24(I2C5_SCL/EDPHDMI_I2C_SCL/GPIO7_C4_u) ; also on sheet 41
I2C5_SDA_HDMI: U1000.H26(I2C5_SDA/EDPHDMI_I2C_SDA/GPIO7_C3_u) ; also on sheet 41
I2S0_CLK: U1000.AC12(I2S_CLK/GPIO6_B0_d) ; also on sheet 31 32 33 34 35
I2S0_LRCK_RX: U1000.AG11(I2S_LRCK_RX/GPIO6_A1_d) ; also on sheet 33 34 35
I2S0_LRCK_TX: U1000.AF11(I2S_LRCK_TX/GPIO6_A2_d) ; also on sheet 33 34 35
I2S0_SCLK: U1000.AD11(I2S_SCLK/GPIO6_A0_d) ; also on sheet 33 34 35
I2S0_SDI: U1000.AE11(I2S_SDI/GPIO6_A3_d) ; also on sheet 33 34 35
I2S0_SDO0: U1000.AG12(I2S_SDO0/GPIO6_A4_d) ; also on sheet 33 34 35
LCD_EN: U1000.F25(GPIO7_A3_d) ; also on sheet 14 29
LCD_RST: U1000.E26(GPIO7_A4_u) ; also on sheet 29
LCDC_BL: U1000.H22(PWM0/GPIO7_A0_d) ; also on sheet 27 28 29 30
LIGHT_INT: U1000.B28(SPI2_CSn1/SC_IO/GPIO8_A3_u) ; also on sheet 43
LVDS_CLK0N: U1000.V28(TRACE_D11/LCDC0_D11/LVDS_CLK0N) ; also on sheet 30
LVDS_CLK0P: U1000.V27(TRACE_D10/LCDC0_D10/LVDS_CLK0P) ; also on sheet 30
LVDS_CLK1N: T1713.1 U1000.Y26(LCDC0_D23/LVDS_CLK1N)
LVDS_CLK1P: T1712.1 U1000.Y25(LCDC0_D22/LVDS_CLK1P)
LVDS_D0N: U1000.T28(TRACE_D1/LCDC0_D1/LVDS_D0N) ; also on sheet 30
LVDS_D0P: U1000.T27(TRACE_D0/LCDC0_D0/LVDS_D0P) ; also on sheet 30
LVDS_D1N: U1000.U28(TRACE_D3/LCDC0_D3/LVDS_D1N) ; also on sheet 30
LVDS_D1P: U1000.U27(TRACE_D2/LCDC0_D2/LVDS_D1P) ; also on sheet 30
LVDS_D2N: U1000.W28(TRACE_D5/LCDC0_D5/LVDS_D2N) ; also on sheet 30
LVDS_D2P: U1000.W27(TRACE_D4/LCDC0_D4/LVDS_D2P) ; also on sheet 30
LVDS_D3N: U1000.Y28(TRACE_D7/LCDC0_D7/LVDS_D3N) ; also on sheet 30
LVDS_D3P: U1000.Y27(TRACE_D6/LCDC0_D6/LVDS_D3P) ; also on sheet 30
LVDS_D4N: T1701.1 U1000.AA28(TRACE_D9/LCDC0_D9/LVDS_D4N)
LVDS_D4P: T1700.1 U1000.AA27(TRACE_D8/LCDC0_D8/LVDS_D4P)
LVDS_D5N: T1703.1 U1000.U26(TRACE_D13/LCDC0_D13/LVDS_D5N)
LVDS_D5P: T1702.1 U1000.U25(TRACE_D12/LCDC0_D12/LVDS_D5P)
LVDS_D6N: T1705.1 U1000.V26(TRACE_D15/LCDC0_D15/LVDS_D6N)
LVDS_D6P: T1704.1 U1000.V25(TRACE_D14/LCDC0_D14/LVDS_D6P)
LVDS_D7N: T1707.1 U1000.AA26(TRACE_CTL/LCDC0_D17/LVDS_D7N)
LVDS_D7P: T1706.1 U1000.AA25(TRACE_CLK/LCDC0_D16/LVDS_D7P)
LVDS_D8N: T1709.1 U1000.AB28(LCDC0_D19/LVDS_D8N)
LVDS_D8P: T1708.1 U1000.AB27(LCDC0_D18/LVDS_D8P)
LVDS_D9N: T1711.1 U1000.AC26(LCDC0_D21/LVDS_D9N)
LVDS_D9P: T1710.1 U1000.AC25(LCDC0_D20/LVDS_D9P)
MIPI_RX_AVDD_1V8: U1000.AC20(MIPI_RX_AVDD_1V8)
MIPI_TX/RX_CLKN: U1000.AF23(MIPI_TX/RX_CLKN) ; also on sheet 25 29
MIPI_TX/RX_CLKP: U1000.AE23(MIPI_TX/RX_CLKP) ; also on sheet 25 29
MIPI_TX/RX_D0N: U1000.AF20(MIPI_TX/RX_D0N) ; also on sheet 25 29
MIPI_TX/RX_D0P: U1000.AE20(MIPI_TX/RX_D0P) ; also on sheet 25 29
MIPI_TX/RX_D1N: U1000.AF21(MIPI_TX/RX_D1N) ; also on sheet 25 29
MIPI_TX/RX_D1P: U1000.AE21(MIPI_TX/RX_D1P) ; also on sheet 25 29
MIPI_TX/RX_D2N: U1000.AF24(MIPI_TX/RX_D2N) ; also on sheet 25 29
MIPI_TX/RX_D2P: U1000.AE24(MIPI_TX/RX_D2P) ; also on sheet 25 29
MIPI_TX/RX_D3N: U1000.AD25(MIPI_TX/RX_D3N) ; also on sheet 25 29
MIPI_TX/RX_D3P: U1000.AF25(MIPI_TX/RX_D3P) ; also on sheet 25 29
MIPI_TX_CLKN: U1000.AE28(MIPI_TX_CLKN) ; also on sheet 28 29
MIPI_TX_CLKP: U1000.AE27(MIPI_TX_CLKP) ; also on sheet 28 29
MIPI_TX_D0N: U1000.AG28(MIPI_TX_D0N) ; also on sheet 28 29
MIPI_TX_D0P: U1000.AG27(MIPI_TX_D0P) ; also on sheet 28 29
MIPI_TX_D1N: U1000.AF28(MIPI_TX_D1N) ; also on sheet 28 29
MIPI_TX_D1P: U1000.AF27(MIPI_TX_D1P) ; also on sheet 28 29
MIPI_TX_D2N: U1000.AD28(MIPI_TX_D2N) ; also on sheet 28 29
MIPI_TX_D2P: U1000.AD27(MIPI_TX_D2P) ; also on sheet 28 29
MIPI_TX_D3N: U1000.AC28(MIPI_TX_D3N) ; also on sheet 28 29
MIPI_TX_D3P: U1000.AC27(MIPI_TX_D3P) ; also on sheet 28 29
OSC_XVSS: C1101.2 C1102.2 R1102.2 U1000.P26(OSC_XVSS) Y1100.2(GND) Y1100.4(GND)
OTG_DET: C2002.2 R2002.1 R2003.2 R2004.2 ; also on sheet 46
OTG_DM: FB2000.2 R2000.1 ; also on sheet 46
OTG_DP: FB2000.4 R2001.1 ; also on sheet 46
OTG_ID: ED2000.1 J2000.4(ID) P2000.1 ; also on sheet 46
OTG_VBUS_DRV: U1000.M28(PMUGPIO0_B4_d) ; also on sheet 13 14
PHONE_CTL: U1000.L27(PMUGPIO0_B3_d) ; also on sheet 33
PMIC_INT: U1000.K28(PMUGPIO0_A4_u) ; also on sheet 13 14
PMIC_SLEEP: U1000.J28(GLOBAL_PWROFF/PMUGPIO0_A0_d) ; also on sheet 13 14
PMIC_VSEL: U1000.G23(PWM1/GPIO7_A1_d) ; also on sheet 14
PWR_HOLD: U1000.L26(OTP_OUT/PMUGPIO0_B2_d) ; also on sheet 14
PWR_KEY: U1000.L21(PMUGPIO0_A5_u) ; also on sheet 14
RESET: C1100.2 U1000.M27(NPOR) ; also on sheet 13 14
RTC_CLKOUT1: U1000.P25(CLKIN_32K) ; also on sheet 13 14
SDMMC_CLK: U1000.AG6(JTAG_TDO/SDMMC0_CLKOUT/GPIO6_C4_d) ; also on sheet 40
SDMMC_CMD: U1000.AC8(SDMMC0_CMD/GPIO6_C5_u) ; also on sheet 40
SDMMC_D0: U1000.AG7(JTAG_TMS/SDMMC0_D0/GPIO6_C0_u) ; also on sheet 40
SDMMC_D1: U1000.AH6(JTAG_TRSTN/SDMMC0_D1/GPIO6_C1_u) ; also on sheet 40
SDMMC_D2: U1000.AD8(JTAG_TDI/SDMMC0_D2/GPIO6_C2_u) ; also on sheet 40
SDMMC_D3: U1000.AB9(JTAG_TCK/SDMMC0_D3/GPIO6_C3_u) ; also on sheet 40
SDMMC_DET: U1000.AH5(SDMMC0_DET/GPIO6_C6_u) ; also on sheet 40
SDMMC_PWR: U1000.E28(eDP_HOTPLUG/GPIO7_B3_d) ; also on sheet 14
SPK_CTL: U1000.G27(ISP_SHUTTERTRIG/SPI1_TXD/GPIO7_B7_d) ; also on sheet 33
TOUCH_INT: U1000.F26(GPIO7_A6_u) ; also on sheet 36 37 38 39
TOUCH_RST: U1000.G24(GPIO7_A5_d) ; also on sheet 36 37 38 39
UART0_CTS: U1000.AB12(UART0_CTSn/GPIO4_C2_u) ; also on sheet 44 47 48
UART0_RTS: U1000.AB11(UART0_RTSn/GPIO4_C3_u) ; also on sheet 44 47 48
UART0_RXD: U1000.AH11(UART0_RXD/GPIO4_C0_u) ; also on sheet 44 47 48
UART0_TXD: U1000.AG10(UART0_TXD/GPIO4_C1_d) ; also on sheet 44 47 48
UART1_CTS: U1000.AH4(UART1_CTSn/TS0_D2/GPIO5_B2_u) ; also on sheet 32
UART1_RTS: U1000.AD6(UART1_RTSn/TS0_D3/GPIO5_B3_u) ; also on sheet 32
UART1_RX: U1000.AF5(UART1_RX/TS0_D0/GPIO5_B0_u) ; also on sheet 31 32
UART1_TX: U1000.AA7(UART1_TX/TS0_D1/GPIO5_B1_d) ; also on sheet 31 32
UART2_RXD: ED1800.1 J1800.1 R1800.2 T1800.1 U1000.J25(UART2_RX/IR_RX/PWM2/GPIO7_C6_u)
UART2_TXD: ED1801.1 J1800.2 T1801.1 U1000.H28(UART2_TX/IR_TX/PWM3/EDPHDMI_CEC/GPIO7_C7_u)
USB_INT: R2003.1 U1000.M24(PMUGPIO0_C2_u)
VIB_CTL: U1000.H27(GPIO7_C5_d) ; also on sheet 43
VREF_DDR0: C1204.1 R1208.2 R1210.2 U1000.H12(DDR0_VREF) ; also on sheet 17 18 19 20
VREF_DDR1: C1209.1 R1209.2 R1211.2 U1000.M8(DDR1_VREF) ; also on sheet 17 18 19 20
VREFAO_DDR0: C1210.2 C1212.1 C1213.1 R1212.2 R1214.2 U1000.H11(DDR0_VREFAO) ; also on sheet 15 16 17 18 19 20
VREFAO_DDR1: C1211.2 C1214.1 C1215.2 R1213.2 R1215.2 U1000.L8(DDR1_VREFAO) ; also on sheet 15 16 17 18 19 20
WIFI_CLK: U1000.AG8(SDIO0_CLKOUT/GPIO4_D1_d) ; also on sheet 44 47 48
WIFI_CMD: U1000.AH8(SDIO0_CMD/GPIO4_D0_u) ; also on sheet 44 47 48
WIFI_D0: U1000.AH9(SDIO0_D0/GPIO4_C4_u) ; also on sheet 44 47 48
WIFI_D1: U1000.AH10(SDIO0_D1/GPIO4_C5_u) ; also on sheet 44 47 48
WIFI_D2: U1000.AG9(SDIO0_D2/GPIO4_C6_u) ; also on sheet 44 47 48
WIFI_D3: U1000.AH7(SDIO0_D3/GPIO4_C7_u) ; also on sheet 44 47 48
WIFI_HOST_WAKE: U1000.AE8(SDIO0_INTn/GPIO4_D6_u) ; also on sheet 44 47 48
WIFI_PWR: U1000.H23(GPS_RFCLK/GPS_CLK_T1/UART3_CTSn/GPIO7_B1_u) ; also on sheet 14
WIFI_REG_ON: U1000.AC11(SDIO0_PWR/GPIO4_D4_d) ; also on sheet 44 47 48
N60605209: R1200.1 U1000.G17(DDR0_PZQ)
N60606815: R1201.1 U1000.U7(DDR1_PZQ)
N60864190: R1704.1 U1000.AD22(MIPI_TX/RX_REXT)
N60864382: R1701.1 U1000.AE26(MIPI_TX_REXT)
N60874407: R1700.1 U1000.AB17(HDMI_EXTR)
N60967477: R1702.1 U1000.V24(LVDS_EXTR)
N61213640: C1101.1 R1100.2 U1000.N27(OSC_XI) Y1100.3(XOUT)
N61213641: C1102.1 R1101.1 Y1100.1(XIN)
N61213645: R1100.1 R1101.2 U1000.N28(OSC_XO)
N61215829: FB2000.3 J2000.3(DP) P2001.1 R2001.2 U2000.2
N61215835: FB2000.1 J2000.2(DM) P2002.1 R2000.2 U2000.1
N61234680: C1704.1 R1703.1 U1000.AB23(LVDS_AVDD_3V3)
N61235685: T1714.1 U1000.AC17(eDP_CLK24M_IN)
N61841107: R1300.2 U1000.Y8(FLASH0_VOLTAGE_SEL/GPIO3_C3_d)

Not connected (* = marked no-connect by the designer): U1000 AA9(TS0_VALID/GPIO5_C1_d)* AA12(eDP_TP_OUT)* AA22(LCDC0_DEN/GPIO1_D2_d)* AA23(LCDC0_HSYNC/GPIO1_D0_d)* AA24(LCDC0_DCLK/GPIO1_D3_d)* AB24(LCDC0_VSYNC/GPIO1_D1_d)* AC18(eDP_EXTR)* AD21(MIPI_RX_REXT)* AE6(TS0_CLK/GPIO5_C2_d)* AE9(SDIO0_WP/GPIO4_D3_d)* AE12(SPDIF_TX/GPIO6_B3_d)* AG13(I2S_SDO2/GPIO6_A6_d)* AG23(MIPI_RX_D0P)* AG24(MIPI_RX_D1P)* AG25(MIPI_RX_CLKP)* AG26(MIPI_RX_D2P)* AH12(I2S_SDO3/GPIO6_A7_d)* AH13(I2S_SDO1/GPIO6_A5_d)* AH23(MIPI_RX_D0N)* AH24(MIPI_RX_D1N)* AH25(MIPI_RX_CLKN)* AH26(MIPI_RX_D2N)* AH27(MIPI_RX_D3N)* AH28(MIPI_RX_D3P)* C28(SPI2_TXD/SC_CLK_T1/GPIO8_B1_d)* D26(SPI2_CLK/SC_IO_T1/GPIO8_A6_d)* D27(SPI2_CSn0/SC_DET_T1/GPIO8_A7_u)* E22(BS_JTAG_TRSTn)* E23(BS_JTAG_TCK)* F21(BS_JTAG_TDI)* F22(BS_JTAG_TDO)* F24(SPI2_RXD/SC_RST_T1/GPIO8_B0_d)* G11(NC3)* G12(DDR0_ATO)* G14(NC1)* G15(NC2)* G20(BS_JTAG_TMS)* H15(DDR0_DTO1)* H17(DDR0_DTO0)* L7(NC6)* L28(CLK27M_IN/PMUGPIO0_B5_d)* M7(DDR1_ATO)* M22(PMUGPIO0_B6_d)* P7(NC4)* R7(NC5)* R8(DDR1_DTO1)* U8(DDR1_DTO0)* U23(HOST_D4/TS_D6/CIF_D8/GPIO2_A6_d)* V7(HOST_D15/MAC_TXCLK/SDIO1_PWREN/FLASH1_CSn2/GPIO4_B1_u)* V23(HOST_D5/TS_D7/CIF_D9/GPIO2_A7_d)*

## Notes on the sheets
sheet 1
- RK3288 REF V1.2
- 01.Index
  02.Change List
  03.Block Diagram
  04.Power Tree-RC5T620
  05.Power Tree-ACT8846
  10.RK3288 Power
  11.RK3288 PMU Controler
  12.RK3288 DDR Controler
  13.RK3288 Flash Controler
  14.RK3288 USB/HSIC Controler
  15.RK3288 SARADC/Key Board
  16.RK3288 DVP Interface
  17.RK3288 Display Interface
  18.RK3288 GPIO
  20.USB Port
  21.Power-RT5C620_1CELL
  22.Power-ACT8846_2CELL (option)
  30.RAM-DDR3 4x16bit
  32.RAM-DDR3 2x32bit (option)
  33.RAM-LPDDR2(168P) (option)
  34.RAM-LPDDR2(220P) (option)
  35.RAM-LPDDR3(178P) (option)
  40.Memory-eMMC
  41.Memory-Nand FLASH (option)
  42.Memory-tSD (option)
  45.DVP power and Flash LED
  46.Camera-MIPI CSI
  47.Camera-CIF (option)
  50.LCM-eDP Panel
  51.LCM-MIPI Panel (option)
  52.LCM-Dual MIPI Panel (option)
  53.LCM-LVDS Panel (option)
  60.WIFI/BT-AP6210
  61.WIFI ac/BT-AP6335 (option)
  62.WIFI/BT/GPS-AP6476 (option)
  65.3G-UNA
  66.3G-UNA LITE (option)
  70.Audio Codec-ES8323
  71.Audio Codec-ALC5631 (option)
  72.Audio Codec-ALC3224 (option)
  75.TP COF
  76.TP COB-CT363 (option)
  77.TP COB-FT5506 (option)
  78.TP COB-GSL3680 (option)
  80.Sensor/VIB
  81.TF Card
  82.HDMI Port
  84.eFUSE (option)
- I2C address(7bit):
  1.I2C0 POWER:
  ACT8846     0x5a
  CW2013      0x62
  HYM8563    0x51
  RT5C620     0x32
  SYR827       0x40
  SYR828       0x41
  2.I2C1 Sensor:
  CM3218        0x10,0x0c
  LSM330TR   G:0x6a  A:0x1e
  MMA8452Q  0X1d
  MPU6050C   0x68
  LIS3DH          0X19
  LSM303D      0X1d
  3.I2C2 Audio Codec:
  ALC3224       0x19
  ALC5623       0x1a
  ALC5631       0x1a
  ES8323          0x10
  4.I2C3 Camera:
  OV2659          0x30
  OV8825          0x36
  5.I2C4 Touch:
  CT363          0x1b
  FT5506
  GSL3680      0x40
sheet 2
- Version
- Date
- Author
- Change Note
- Approved
- V1.0
- 20140429
- LX
- First edictor
- V1.1
- 20140625
- LX
- Please refer to document of 《RK3288发布原理图修改点 V11 20140625》
- V1.2
- 20140806
- LX
- Please refer to document of 《RK3288发布原理图修改点 V12 20140806》
- Note:GPIO外部所接是开漏信号或者利用GPIO上下拉默认状态做特定功能的，
  有可能出现小概率的不确定状态，外部需要增加或预留上拉或下拉电阻以确定状态。
sheet 3
- Block Diagram for MID
- HDMI
- Display PANEL
- I2C0
- HDMI
- LVDS
- eDP
- MIPI TX
- LCDC
- Over-
  Temperature
  Protection
- OTP Reset
- UART3
- GPS
- POWER Manage
- SYSTEM
  POWER
- UART1
  SPI0
- 3G Module
- 32.768KHz
- 32K CLKIN
  &RESET IN
- UART2
- UART DEBUG
- RK3288 CORE
- 32.768KHz
- OSC 24M
- USB OTG
- OTG 2.0
- SDIO0
  UART0
- WIFI/BT
- USB HOST1
- USB 2.0
- MIPI RX
  &DVP
  I2C3
- CAMERA
- USB HOST2
- USB 2.0/1.1
- I2S
  I2C2
- SDMMC0
  &JTAG
- AUDIO CODEC
- TF Card
  &JTAG
- GPIO
- HSIC
- I2C4
- FLASH1
  &GMAC
- FLASH0
- DDR0
- DDR1
- Touch Panel
- ADC
- I2C1
- KEYBOARD
- RGMII PHY
- Nand Flash
  eMMC Flash
  tSD Flash
- 32bit DDR3
  LPDDR2
  LPDDR3
- 32bit DDR3
  LPDDR2
  LPDDR3
- G-SENSOR
  COMPASS
  Gyroscope
sheet 4
- VCC_DDR
- VP1
- BUCK1
- RK3288 DDR-Ctrl
- DDR3 Device
- 12V/2A
  Input
- VCC_IO
- RK3288 IO Supply
- FLASH
- VP2
- BUCK2
- RK3288 LVDS
- VDD_LOG
- VP3
- BUCK3
- CPU Logic
- VCC_20
- VCC_SYS
- VP4
- BUCK4
- Supply
- CHARGE&
  POWER SWITCH
- 5V/2.5A
- VCCIO_SD
- OUT5
- RK3288 SDIO-Ctrl
- VCC_IO
- INL1
- VDD10_LCD
- RK3288 eDP
- OUT6
- RK3288 LVDS
- RK3288 HDMI
- OUT7
- VCCA_CODEC
- AUDIO CODEC
- VCC_TP
- OUT8
- Touch IC
- INL2
- OUT9
- VCCIO_PMU
- RK3288 IO Supply
- RK3288 USB PHY
- VDD_10
- RK3288 PLL
- OUT10
- RK3288 USB PHY
- RK3288 SAR-ADC
- VCC_18
- VCC_20
- OUT11
- RK3288 USB PHY
- INL3
- LPDDR Device
- Sensor
- RK3288 MIPI TX
- VCC18_LCD
- OUT12
- RK3288 MIPI TX/RX
- RK3288 eDP
- RK3288 LVDS
- OUT13
- RK3288 HDMI
- ACT8846
- VDD_CPU
- DC/DC SYR827
- CPU
- VDD_GPU
- DC/DC SYR828
- GPU
- HDMI_5V
- VCC33_RTC
- 32K CLKOUT
- LDO
- RK3288
- RTC
- WIFI+BT
- VCC50_USB
- Switch
- USB OTG
- VCC18_DVP
- LDO
- VCC28_DVP
- LDO
- CAMERA
- LDO
- VCC15_DVP
- VCC_SD
- MOS
- SD CARD
- MOS
- VCC_WL
- WIFI+BT
- VCC_LCD
- MOS
- Display Panel
sheet 5
- RK3288 FILTER
sheet 7
- RK3288 DDR Channel-0
- RK3288 DDR Channel-1
- RK3288_K
- RK3288_L
sheet 8
- Note:VCC_FLASH (The supply may be 1.8V or3.0V,
       and must be connected to RK3288 FLASH_VDD).
sheet 10
- Note:Placed close to
  the transmitter side
sheet 12
- USB OTG
- USB Detection
